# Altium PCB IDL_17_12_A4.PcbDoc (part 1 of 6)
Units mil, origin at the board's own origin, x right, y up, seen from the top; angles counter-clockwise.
Board outline 3172.06 x 10350 mil, 6 copper layers (Top Signal, Mid Signal, 3.3 Volt, GND, 5 Volt, Bot Signal), stack 122.8 mil thick; 332 components, 120 nets, 1937 pads, 197 vias.
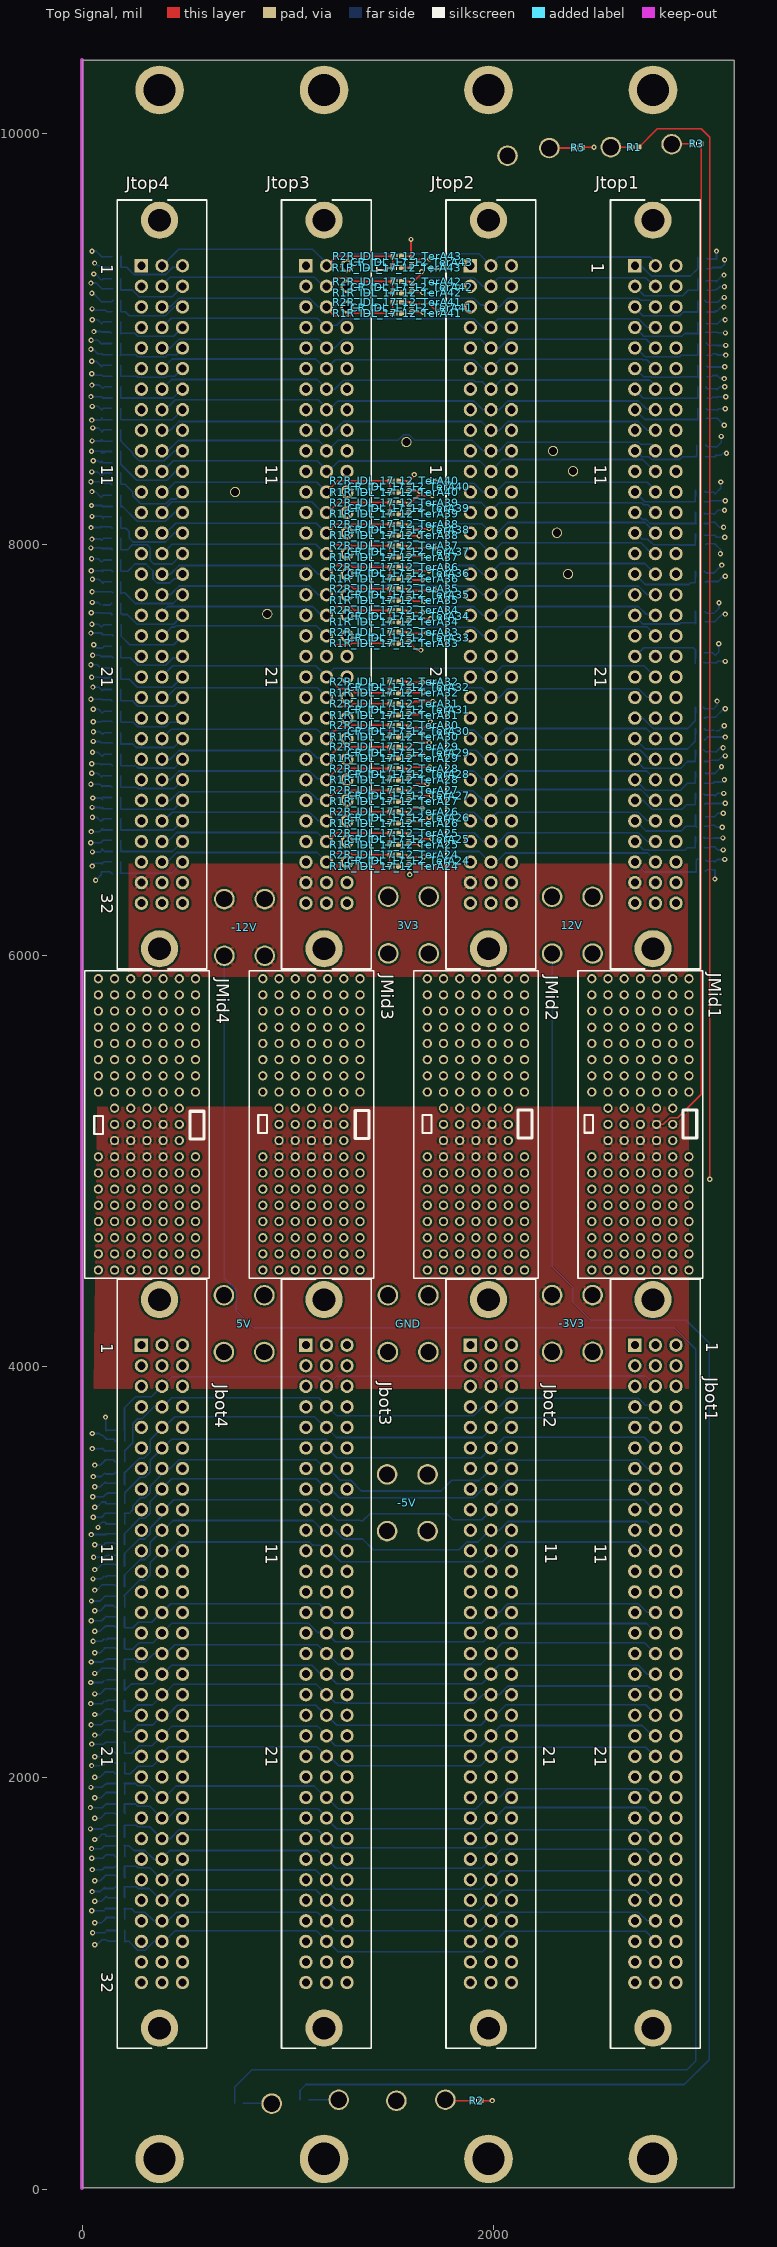
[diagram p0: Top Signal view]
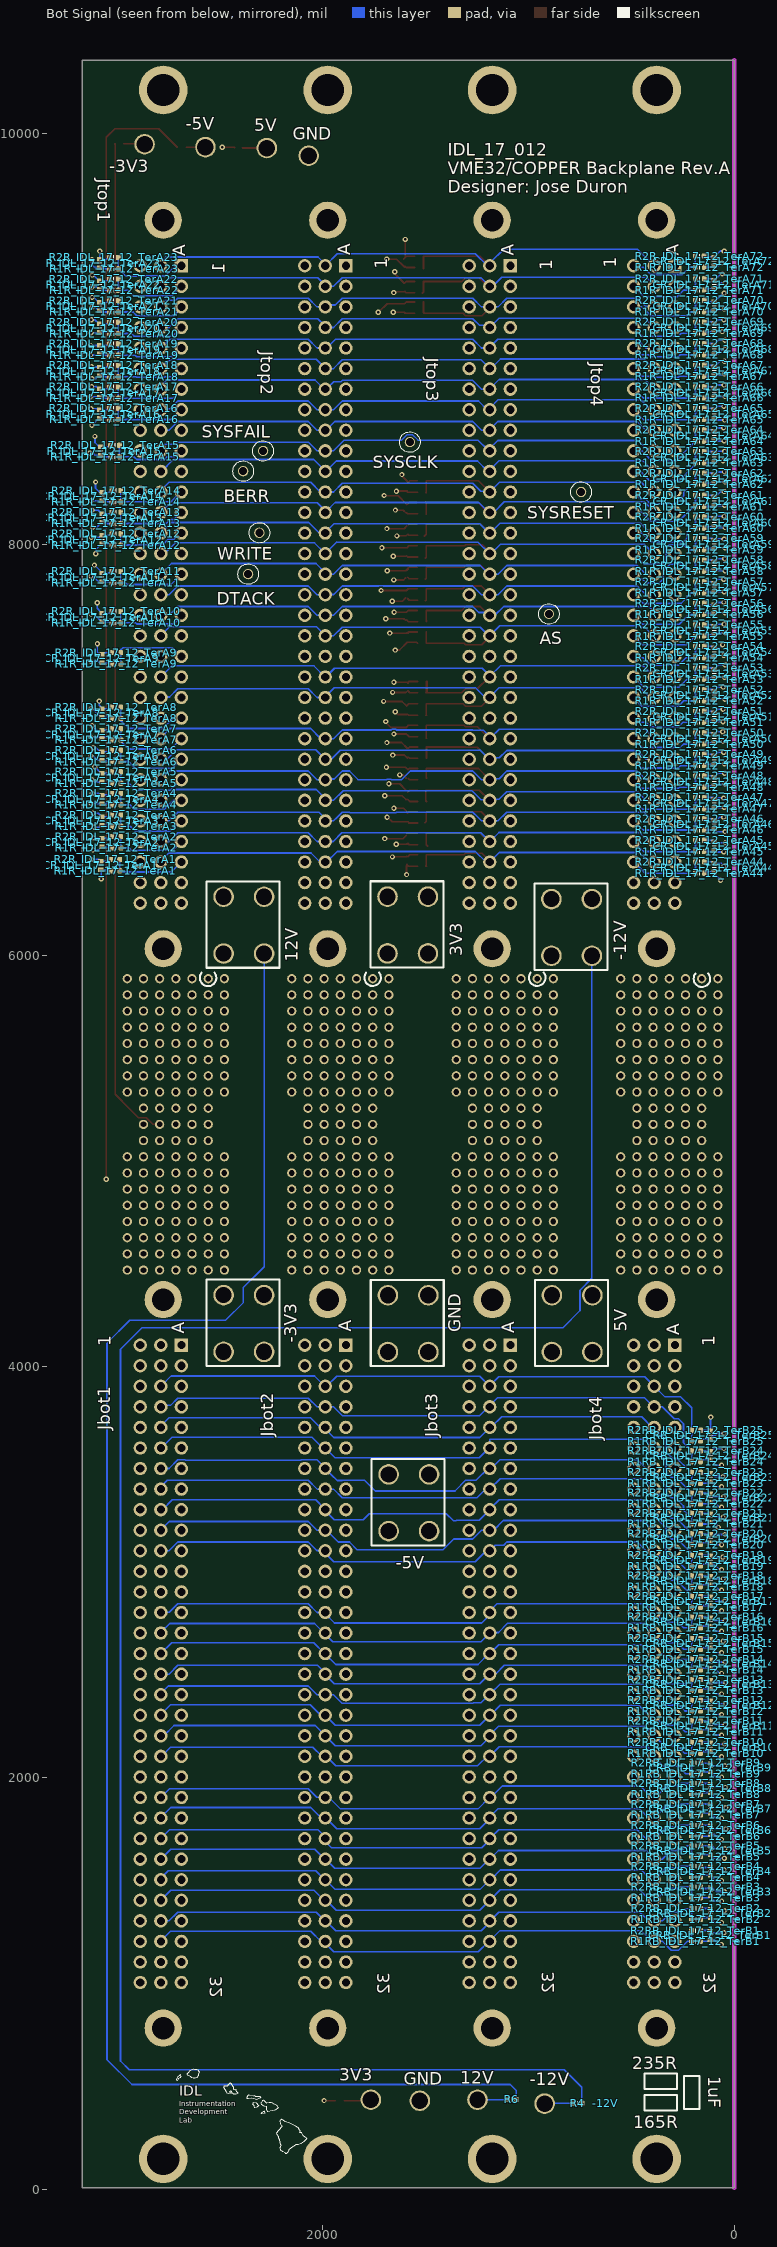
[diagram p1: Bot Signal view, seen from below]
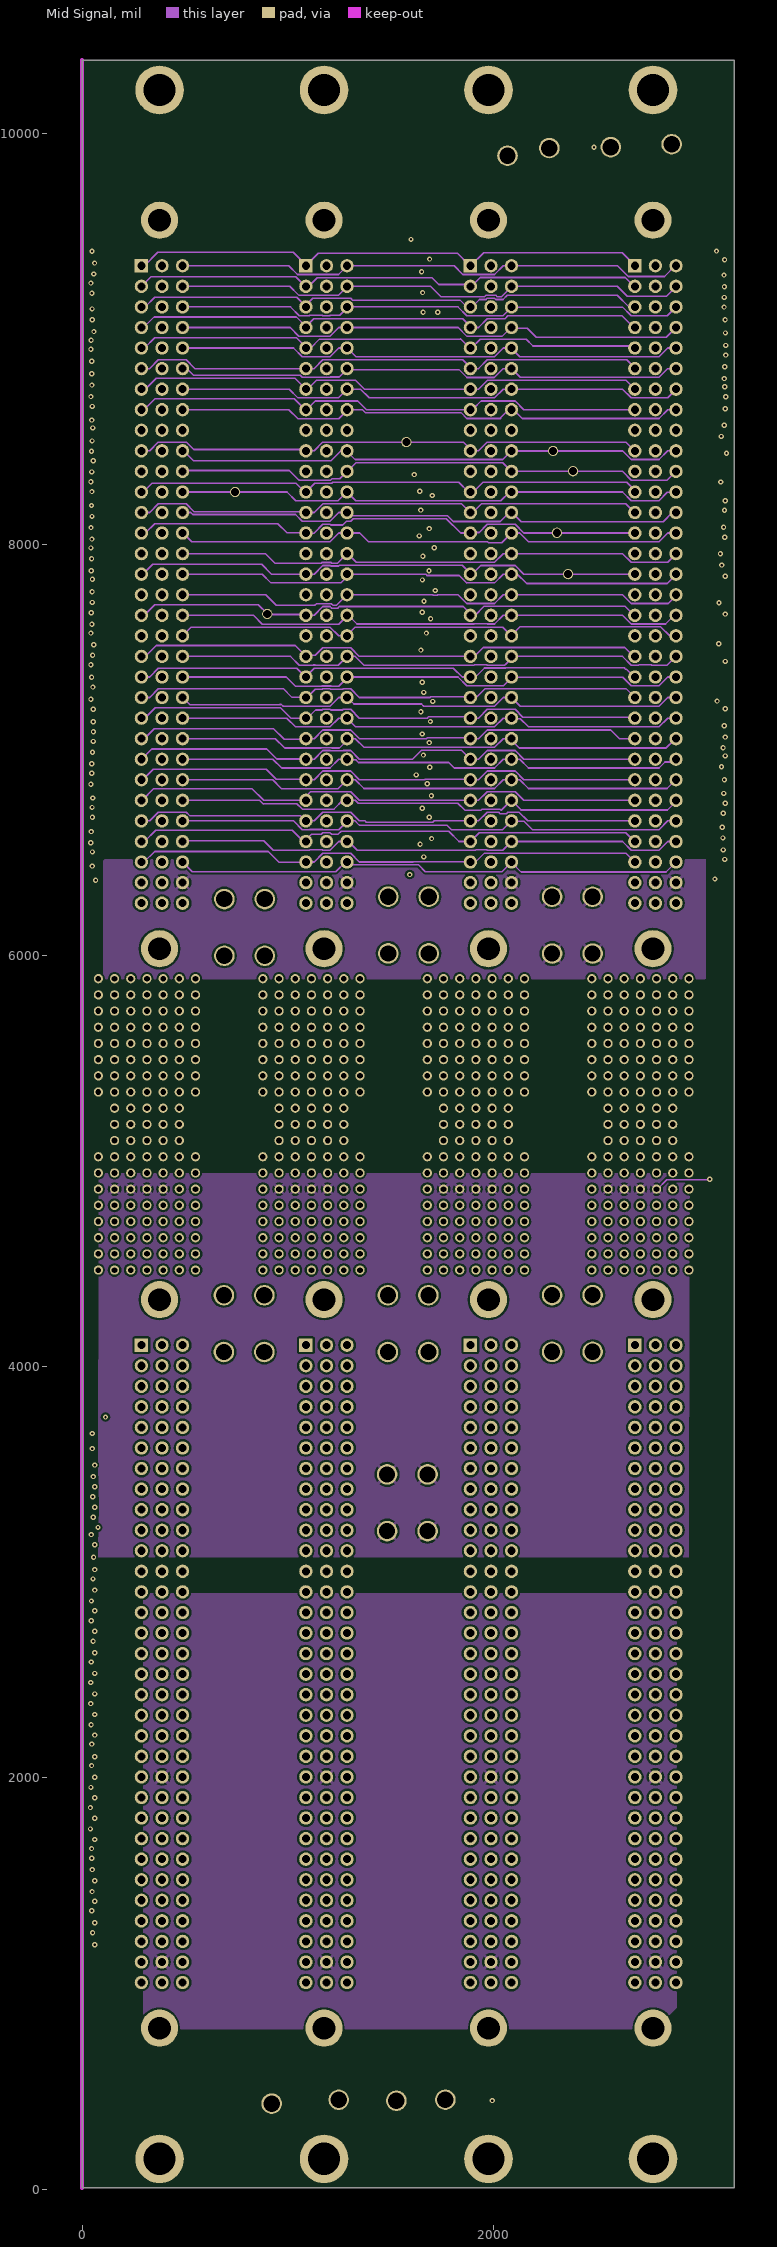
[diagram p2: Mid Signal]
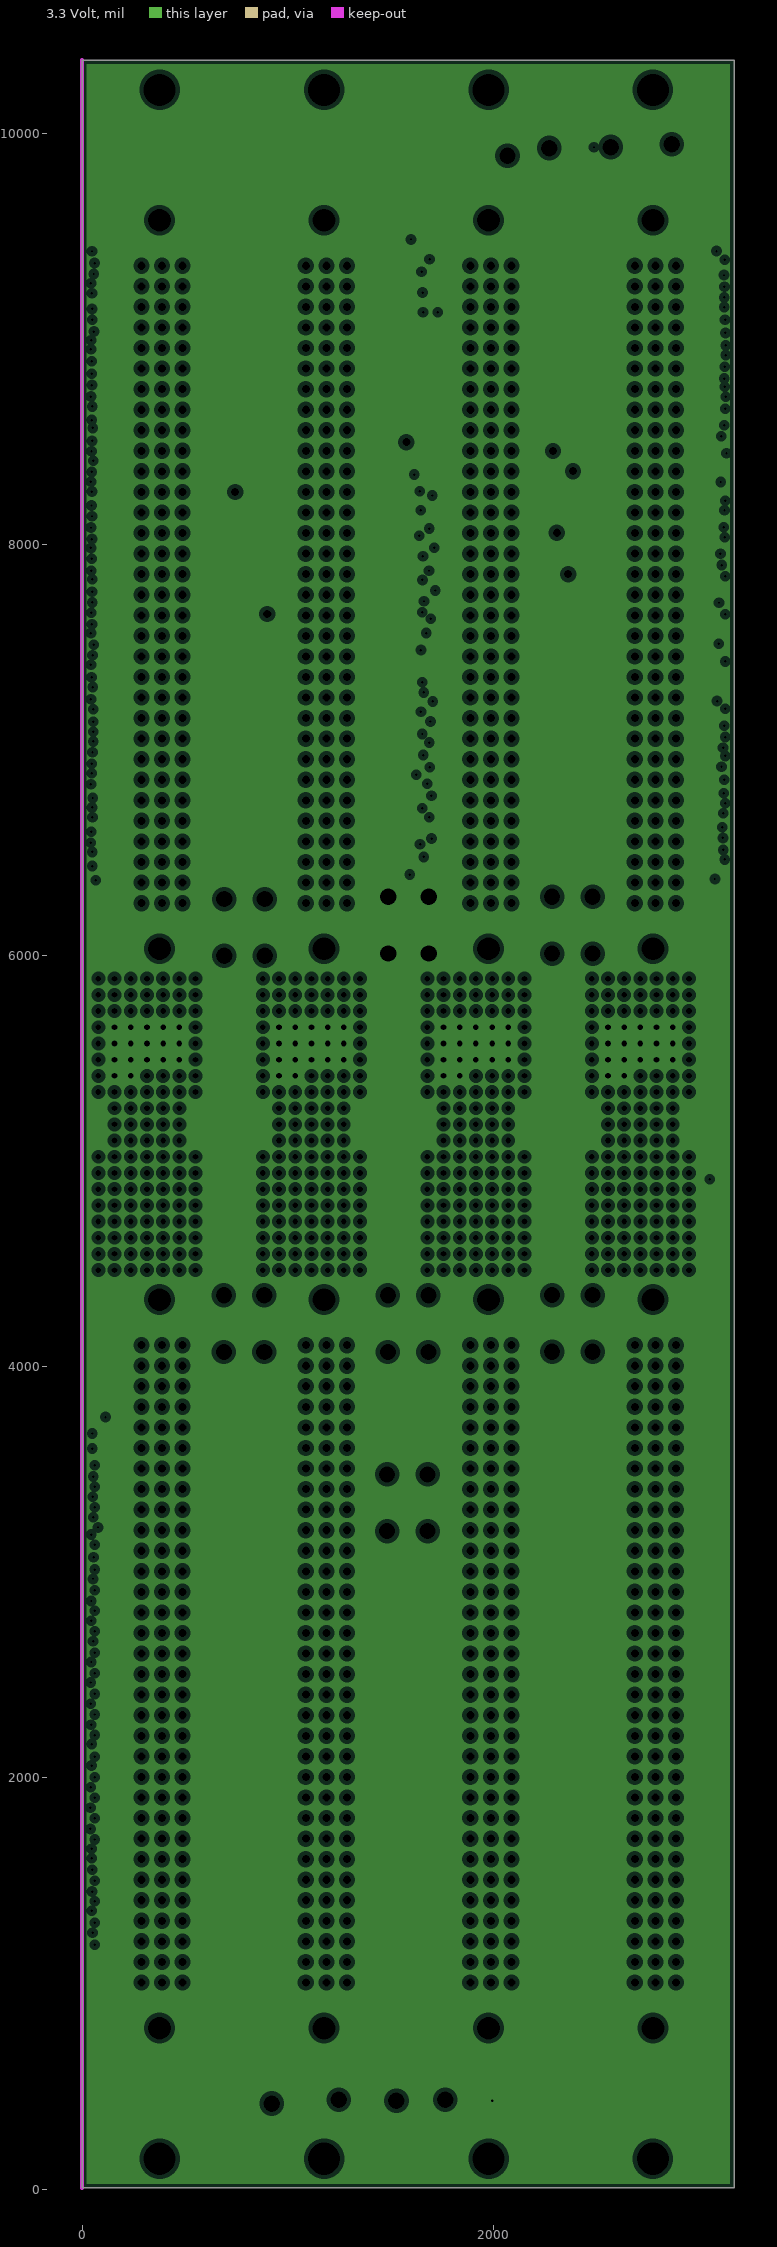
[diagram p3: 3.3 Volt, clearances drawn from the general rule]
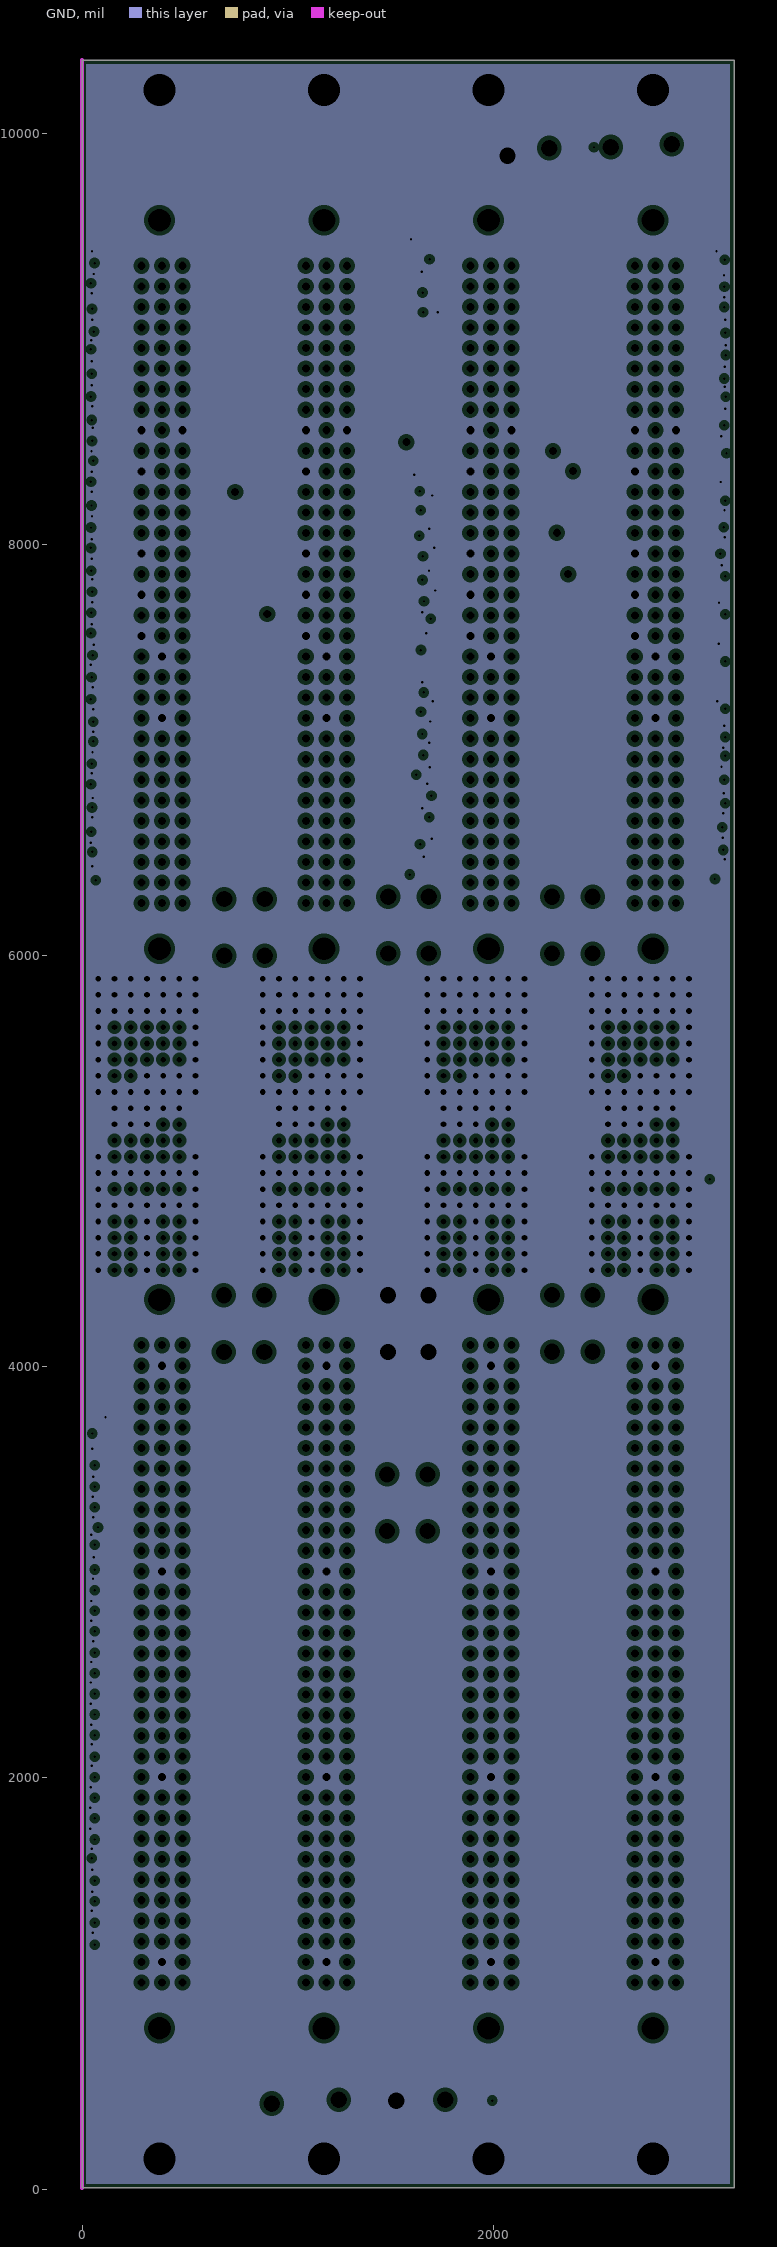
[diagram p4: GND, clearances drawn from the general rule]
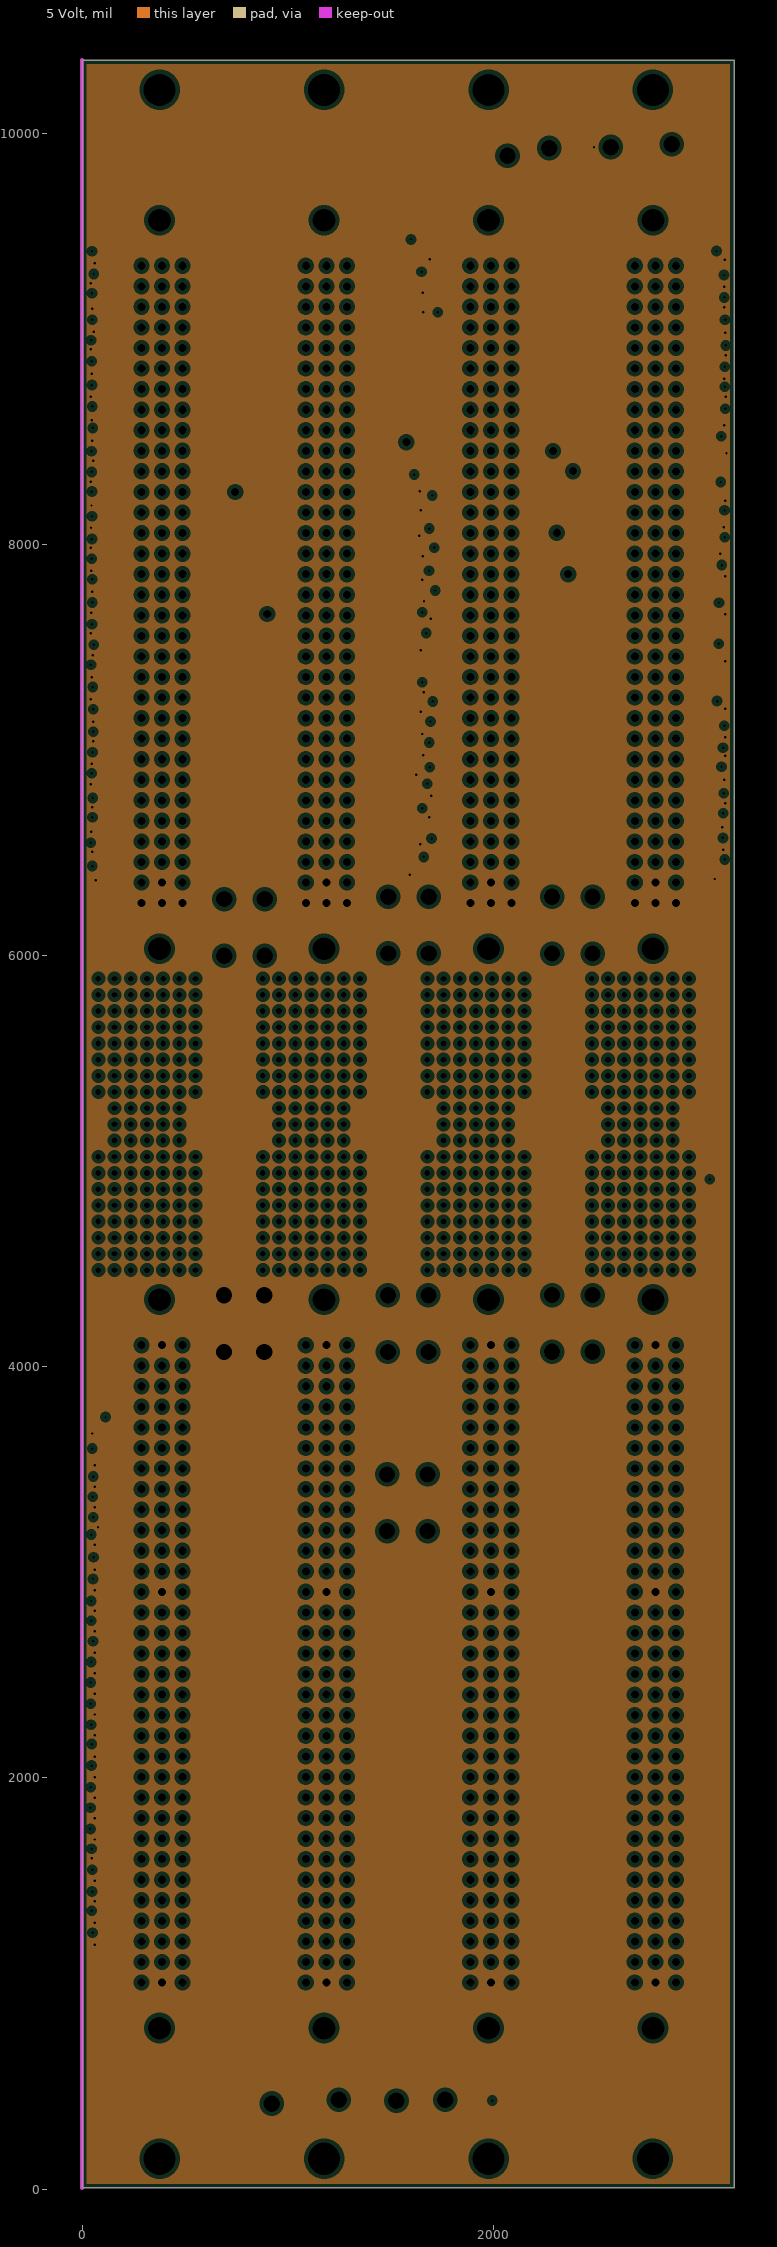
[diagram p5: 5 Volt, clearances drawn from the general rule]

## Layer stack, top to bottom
Top Solder: solder mask 0.4, Solder Resist, Dk 3.5
Top Signal: signal copper 1.35
Dielectric 1: prepreg 10, FR-4, Dk 4.2
Mid Signal: signal copper 1.35
Dielectric 6: core 40, FR-4, Dk 4.2
3.3 Volt: plane copper 2.7, net 3V3
Dielectric 5: prepreg 12, FR-4, Dk 4.2
GND: plane copper 2.7, net GND
Dielectric2: core 40, FR-4, Dk 4.2
5 Volt: plane copper 1.35, net 5V
Dielectric 7: prepreg 10, Dk 4.2
Bot Signal: signal copper 1.35
Bottom Solder: solder mask 0.4, Solder Resist, Dk 3.5

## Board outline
-0.72,10355.73 3171.34,10355.73 3171.34,5.73 -0.72,5.73

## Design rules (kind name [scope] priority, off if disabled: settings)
Clearance "Clearance Polygon" [InNamedPolygon('-12V') or InNamedPolygon('12V')or InNamedPolygon('-3V3')or InNamedPolygon('-5V')or InNamedPolygon('Mid Signal-No Net')] p1: gap=10 ignorepadtopadclearanceinfootprint=FALSE
Clearance "Clearance - Default - DEFAULT- SMD" [IsVia vs IsSMTPin] p2: gap=6 ignorepadtopadclearanceinfootprint=FALSE
Clearance "Clearance - Default - DEFAULT - Via" [IsVia vs IsVia] p3: gap=6 ignorepadtopadclearanceinfootprint=FALSE
Clearance "Clearance - Default - DEFAULT - Net" [All] p4: gap=6 ignorepadtopadclearanceinfootprint=FALSE except(0: Arc-Hole Track-Hole SMDPad-Hole THPad-Hole Via-Hole Fill-Hole Poly-Hole Region-Hole Text-Hole; 10: Text-Text)
ComponentClearance "ComponentClearance - Default - DEFAULT" [All] p1: gap=6 collisioncheckmode=3 verticalgap=10 showdistances=FALSE
DiffPairsRouting [All] p1: maxlimit=10 minlimit=4.02 mostfreqgap=6 toplayer_minwidth=4.02 toplayer_maxwidth=10 toplayer_prefwidth=8 midlayer1_minwidth=4.02 midlayer1_maxwidth=10 midlayer1_prefwidth=8 bottomlayer_minwidth=4.02 bottomlayer_maxwidth=10 bottomlayer_prefwidth=8 maxuncoupledlength=500
FanoutControl Fanout_Small [(CompPinCount < 5)] p3: bgadir=Out bgaviamode=Centered fanoutstyle=Auto fanoutdirection=OutThenIn viagrid=1 // Fanout_Small (Default Rule)
FanoutControl Fanout_SOIC [IsSOIC] p4: bgadir=Out bgaviamode=Centered fanoutstyle=Auto fanoutdirection=Alternating viagrid=1 // Fanout_SOIC (Default Rule)
HoleSize [All] p1: absolutevalues=TRUE maxlimit=200 minlimit=1 maxpercent=80.000 minpercent=20.000
HoleToHoleClearance "HoleToHoleClearance - Default - DEFAULT" [All] p1: gap=6 allowstackedmicrovias=TRUE
Length "Default Length" [All] p1: maxlimit=50000 minlimit=0
MaxMinImpedance "Default Impedance" [All] p1: minimum=50.00 maximum=150.0
MinimumSolderMaskSliver [All] p1: minsoldermaskwidth=5
ParallelSegment "Default Parallel Segment Adjasent" [All] p1: limit=1000 gap=200
ParallelSegment "Default Parallel Segment Same Layer" [All] p2: limit=1000 gap=200
PlaneClearance [All] p1: clearance=20
PlaneConnect "Default PlaneConnect" [All] p1: planeconnectstyle=Relief reliefexpansion=20 reliefentries=4 reliefconductorwidth=15 reliefairgap=10
PolygonConnect "PolygonConnect - Default SMT" [IsSMTPin] p1: connectstyle=Relief reliefconductorwidth=10 reliefentries=4 polygonreliefangle="45 Angle" airgapwidth=10
PolygonConnect "PolygonConnect - Default Pad" [All] p2: connectstyle=Relief reliefconductorwidth=15 reliefentries=4 polygonreliefangle="45 Angle" airgapwidth=10
RoomDefinition IDL_17_12_TerA72 [InComponentClass('IDL_17_12_TerA72')] p1 off: confinementstyle=ConfineIn formatcopy=TRUE lockcomponents=FALSE outline 5386.99,6056.96 5550.78,6056.96 5550.78,6176.38 5386.99,6176.38
RoomDefinition IDL_17_12_TerB25 [InComponentClass('IDL_17_12_TerB25')] p2 off: confinementstyle=ConfineIn formatcopy=TRUE lockcomponents=FALSE outline 3621.28,1764.19 3769.76,1764.19 3769.76,1655.73 3621.28,1655.73
RoomDefinition IDL_17_12_TerB24 [InComponentClass('IDL_17_12_TerB24')] p3 off: confinementstyle=ConfineIn formatcopy=TRUE lockcomponents=FALSE outline 3621.28,1864.19 3769.76,1864.19 3769.76,1755.73 3621.28,1755.73
RoomDefinition IDL_17_12_TerB23 [InComponentClass('IDL_17_12_TerB23')] p4 off: confinementstyle=ConfineIn formatcopy=TRUE lockcomponents=FALSE outline 3621.28,1969.19 3769.76,1969.19 3769.76,1860.73 3621.28,1860.73
RoomDefinition IDL_17_12_TerB22 [InComponentClass('IDL_17_12_TerB22')] p5 off: confinementstyle=ConfineIn formatcopy=TRUE lockcomponents=FALSE outline 3621.28,2069.19 3769.76,2069.19 3769.76,1960.73 3621.28,1960.73
RoomDefinition IDL_17_12_TerB21 [InComponentClass('IDL_17_12_TerB21')] p6 off: confinementstyle=ConfineIn formatcopy=TRUE lockcomponents=FALSE outline 3621.28,2167.19 3769.76,2167.19 3769.76,2058.73 3621.28,2058.73
RoomDefinition IDL_17_12_TerB20 [InComponentClass('IDL_17_12_TerB20')] p7 off: confinementstyle=ConfineIn formatcopy=TRUE lockcomponents=FALSE outline 3621.28,2267.19 3769.76,2267.19 3769.76,2158.73 3621.28,2158.73
RoomDefinition IDL_17_12_TerB19 [InComponentClass('IDL_17_12_TerB19')] p8 off: confinementstyle=ConfineIn formatcopy=TRUE lockcomponents=FALSE outline 3621.28,2372.19 3769.76,2372.19 3769.76,2263.73 3621.28,2263.73
RoomDefinition IDL_17_12_TerB18 [InComponentClass('IDL_17_12_TerB18')] p9 off: confinementstyle=ConfineIn formatcopy=TRUE lockcomponents=FALSE outline 3621.28,2472.19 3769.76,2472.19 3769.76,2363.73 3621.28,2363.73
RoomDefinition IDL_17_12_TerB17 [InComponentClass('IDL_17_12_TerB17')] p10 off: confinementstyle=ConfineIn formatcopy=TRUE lockcomponents=FALSE outline 3621.28,2572.19 3769.76,2572.19 3769.76,2463.73 3621.28,2463.73
RoomDefinition IDL_17_12_TerB16 [InComponentClass('IDL_17_12_TerB16')] p11 off: confinementstyle=ConfineIn formatcopy=TRUE lockcomponents=FALSE outline 3621.28,2672.19 3769.76,2672.19 3769.76,2563.73 3621.28,2563.73
RoomDefinition IDL_17_12_TerB15 [InComponentClass('IDL_17_12_TerB15')] p12 off: confinementstyle=ConfineIn formatcopy=TRUE lockcomponents=FALSE outline 3621.28,2777.19 3769.76,2777.19 3769.76,2668.73 3621.28,2668.73
RoomDefinition IDL_17_12_TerB14 [InComponentClass('IDL_17_12_TerB14')] p13 off: confinementstyle=ConfineIn formatcopy=TRUE lockcomponents=FALSE outline 3621.28,2877.19 3769.76,2877.19 3769.76,2768.73 3621.28,2768.73
RoomDefinition IDL_17_12_TerB13 [InComponentClass('IDL_17_12_TerB13')] p14 off: confinementstyle=ConfineIn formatcopy=TRUE lockcomponents=FALSE outline 3621.28,2977.19 3769.76,2977.19 3769.76,2868.73 3621.28,2868.73
RoomDefinition IDL_17_12_TerB12 [InComponentClass('IDL_17_12_TerB12')] p15 off: confinementstyle=ConfineIn formatcopy=TRUE lockcomponents=FALSE outline 3621.28,3077.19 3769.76,3077.19 3769.76,2968.73 3621.28,2968.73
RoomDefinition IDL_17_12_TerB11 [InComponentClass('IDL_17_12_TerB11')] p16 off: confinementstyle=ConfineIn formatcopy=TRUE lockcomponents=FALSE outline 3621.28,3177.19 3769.76,3177.19 3769.76,3068.73 3621.28,3068.73
RoomDefinition IDL_17_12_TerB10 [InComponentClass('IDL_17_12_TerB10')] p17 off: confinementstyle=ConfineIn formatcopy=TRUE lockcomponents=FALSE outline 3621.28,3282.19 3769.76,3282.19 3769.76,3173.73 3621.28,3173.73
RoomDefinition IDL_17_12_TerB9 [InComponentClass('IDL_17_12_TerB9')] p18 off: confinementstyle=ConfineIn formatcopy=TRUE lockcomponents=FALSE outline 3621.28,3382.19 3769.76,3382.19 3769.76,3273.73 3621.28,3273.73
RoomDefinition IDL_17_12_TerB8 [InComponentClass('IDL_17_12_TerB8')] p19 off: confinementstyle=ConfineIn formatcopy=TRUE lockcomponents=FALSE outline 3621.28,3482.19 3769.76,3482.19 3769.76,3373.73 3621.28,3373.73
RoomDefinition IDL_17_12_TerB7 [InComponentClass('IDL_17_12_TerB7')] p20 off: confinementstyle=ConfineIn formatcopy=TRUE lockcomponents=FALSE outline 3621.28,3582.19 3769.76,3582.19 3769.76,3473.73 3621.28,3473.73
RoomDefinition IDL_17_12_TerB6 [InComponentClass('IDL_17_12_TerB6')] p21 off: confinementstyle=ConfineIn formatcopy=TRUE lockcomponents=FALSE outline 3621.28,3685.19 3769.76,3685.19 3769.76,3576.73 3621.28,3576.73
RoomDefinition IDL_17_12_TerB5 [InComponentClass('IDL_17_12_TerB5')] p22 off: confinementstyle=ConfineIn formatcopy=TRUE lockcomponents=FALSE outline 3621.28,3785.19 3769.76,3785.19 3769.76,3676.73 3621.28,3676.73
RoomDefinition IDL_17_12_TerB4 [InComponentClass('IDL_17_12_TerB4')] p23 off: confinementstyle=ConfineIn formatcopy=TRUE lockcomponents=FALSE outline 3621.28,3885.19 3769.76,3885.19 3769.76,3776.73 3621.28,3776.73
RoomDefinition IDL_17_12_TerB3 [InComponentClass('IDL_17_12_TerB3')] p24 off: confinementstyle=ConfineIn formatcopy=TRUE lockcomponents=FALSE outline 3621.28,3985.19 3769.76,3985.19 3769.76,3876.73 3621.28,3876.73
RoomDefinition IDL_17_12_TerB2 [InComponentClass('IDL_17_12_TerB2')] p25 off: confinementstyle=ConfineIn formatcopy=TRUE lockcomponents=FALSE outline 3621.28,4090.19 3769.76,4090.19 3769.76,3981.73 3621.28,3981.73
RoomDefinition IDL_17_12_TerB1 [InComponentClass('IDL_17_12_TerB1')] p26 off: confinementstyle=ConfineIn formatcopy=TRUE lockcomponents=FALSE outline 3620.59,4197.67 3769.06,4197.67 3769.06,4089.21 3620.59,4089.21
RoomDefinition IDL_17_12_TerA71 [InComponentClass('IDL_17_12_TerA71')] p27 off: confinementstyle=ConfineIn formatcopy=TRUE lockcomponents=FALSE outline 5386.28,6283.44 5535.39,6283.44 5535.39,6176.73 5386.28,6176.73
RoomDefinition IDL_17_12_TerA70 [InComponentClass('IDL_17_12_TerA70')] p28 off: confinementstyle=ConfineIn formatcopy=TRUE lockcomponents=FALSE outline 5386.28,6388.44 5535.39,6388.44 5535.39,6281.73 5386.28,6281.73
RoomDefinition IDL_17_12_TerA69 [InComponentClass('IDL_17_12_TerA69')] p29 off: confinementstyle=ConfineIn formatcopy=TRUE lockcomponents=FALSE outline 5386.28,6493.44 5535.39,6493.44 5535.39,6386.73 5386.28,6386.73
RoomDefinition IDL_17_12_TerA68 [InComponentClass('IDL_17_12_TerA68')] p30 off: confinementstyle=ConfineIn formatcopy=TRUE lockcomponents=FALSE outline 5386.28,6598.44 5535.39,6598.44 5535.39,6491.73 5386.28,6491.73
RoomDefinition IDL_17_12_TerA67 [InComponentClass('IDL_17_12_TerA67')] p31 off: confinementstyle=ConfineIn formatcopy=TRUE lockcomponents=FALSE outline 5386.28,6703.44 5535.39,6703.44 5535.39,6596.73 5386.28,6596.73
RoomDefinition IDL_17_12_TerA66 [InComponentClass('IDL_17_12_TerA66')] p32 off: confinementstyle=ConfineIn formatcopy=TRUE lockcomponents=FALSE outline 5386.28,6808.44 5535.39,6808.44 5535.39,6701.73 5386.28,6701.73
RoomDefinition IDL_17_12_TerA65 [InComponentClass('IDL_17_12_TerA65')] p33 off: confinementstyle=ConfineIn formatcopy=TRUE lockcomponents=FALSE outline 5386.28,6913.44 5535.39,6913.44 5535.39,6806.73 5386.28,6806.73
RoomDefinition IDL_17_12_TerA64 [InComponentClass('IDL_17_12_TerA64')] p34 off: confinementstyle=ConfineIn formatcopy=TRUE lockcomponents=FALSE outline 5386.28,7018.44 5535.39,7018.44 5535.39,6911.73 5386.28,6911.73
RoomDefinition IDL_17_12_TerA63 [InComponentClass('IDL_17_12_TerA63')] p35 off: confinementstyle=ConfineIn formatcopy=TRUE lockcomponents=FALSE outline 5386.28,7123.44 5535.39,7123.44 5535.39,7016.73 5386.28,7016.73
RoomDefinition IDL_17_12_TerA62 [InComponentClass('IDL_17_12_TerA62')] p36 off: confinementstyle=ConfineIn formatcopy=TRUE lockcomponents=FALSE outline 5386.28,7228.44 5535.39,7228.44 5535.39,7121.73 5386.28,7121.73
RoomDefinition IDL_17_12_TerA61 [InComponentClass('IDL_17_12_TerA61')] p37 off: confinementstyle=ConfineIn formatcopy=TRUE lockcomponents=FALSE outline 5386.28,7336.44 5535.39,7336.44 5535.39,7229.73 5386.28,7229.73
RoomDefinition IDL_17_12_TerA60 [InComponentClass('IDL_17_12_TerA60')] p38 off: confinementstyle=ConfineIn formatcopy=TRUE lockcomponents=FALSE outline 5386.28,7441.44 5535.39,7441.44 5535.39,7334.73 5386.28,7334.73
RoomDefinition IDL_17_12_TerA59 [InComponentClass('IDL_17_12_TerA59')] p39 off: confinementstyle=ConfineIn formatcopy=TRUE lockcomponents=FALSE outline 5386.28,7546.44 5535.39,7546.44 5535.39,7439.73 5386.28,7439.73
RoomDefinition IDL_17_12_TerA58 [InComponentClass('IDL_17_12_TerA58')] p40 off: confinementstyle=ConfineIn formatcopy=TRUE lockcomponents=FALSE outline 5386.28,7651.44 5535.39,7651.44 5535.39,7544.73 5386.28,7544.73
RoomDefinition IDL_17_12_TerA57 [InComponentClass('IDL_17_12_TerA57')] p41 off: confinementstyle=ConfineIn formatcopy=TRUE lockcomponents=FALSE outline 5386.28,7756.44 5535.39,7756.44 5535.39,7649.73 5386.28,7649.73
RoomDefinition IDL_17_12_TerA56 [InComponentClass('IDL_17_12_TerA56')] p42 off: confinementstyle=ConfineIn formatcopy=TRUE lockcomponents=FALSE outline 5386.28,7861.44 5535.39,7861.44 5535.39,7754.73 5386.28,7754.73
RoomDefinition IDL_17_12_TerA55 [InComponentClass('IDL_17_12_TerA55')] p43 off: confinementstyle=ConfineIn formatcopy=TRUE lockcomponents=FALSE outline 5386.28,7966.44 5535.39,7966.44 5535.39,7859.73 5386.28,7859.73
RoomDefinition IDL_17_12_TerA54 [InComponentClass('IDL_17_12_TerA54')] p44 off: confinementstyle=ConfineIn formatcopy=TRUE lockcomponents=FALSE outline 5386.28,8071.44 5535.39,8071.44 5535.39,7964.73 5386.28,7964.73
RoomDefinition IDL_17_12_TerA53 [InComponentClass('IDL_17_12_TerA53')] p45 off: confinementstyle=ConfineIn formatcopy=TRUE lockcomponents=FALSE outline 5386.28,8176.44 5535.39,8176.44 5535.39,8069.73 5386.28,8069.73
RoomDefinition IDL_17_12_TerA52 [InComponentClass('IDL_17_12_TerA52')] p46 off: confinementstyle=ConfineIn formatcopy=TRUE lockcomponents=FALSE outline 5386.28,8281.44 5535.39,8281.44 5535.39,8174.73 5386.28,8174.73
RoomDefinition IDL_17_12_TerA51 [InComponentClass('IDL_17_12_TerA51')] p47 off: confinementstyle=ConfineIn formatcopy=TRUE lockcomponents=FALSE outline 5386.28,8386.44 5535.39,8386.44 5535.39,8279.73 5386.28,8279.73
RoomDefinition IDL_17_12_TerA50 [InComponentClass('IDL_17_12_TerA50')] p48 off: confinementstyle=ConfineIn formatcopy=TRUE lockcomponents=FALSE outline 5386.28,8491.44 5535.39,8491.44 5535.39,8384.73 5386.28,8384.73
RoomDefinition IDL_17_12_TerA49 [InComponentClass('IDL_17_12_TerA49')] p49 off: confinementstyle=ConfineIn formatcopy=TRUE lockcomponents=FALSE outline 5386.28,8596.44 5535.39,8596.44 5535.39,8489.73 5386.28,8489.73
RoomDefinition IDL_17_12_TerA48 [InComponentClass('IDL_17_12_TerA48')] p50 off: confinementstyle=ConfineIn formatcopy=TRUE lockcomponents=FALSE outline 5386.28,8701.44 5535.39,8701.44 5535.39,8594.73 5386.28,8594.73
RoomDefinition IDL_17_12_TerA47 [InComponentClass('IDL_17_12_TerA47')] p51 off: confinementstyle=ConfineIn formatcopy=TRUE lockcomponents=FALSE outline 5386.28,8806.44 5535.39,8806.44 5535.39,8699.73 5386.28,8699.73
RoomDefinition IDL_17_12_TerA46 [InComponentClass('IDL_17_12_TerA46')] p52 off: confinementstyle=ConfineIn formatcopy=TRUE lockcomponents=FALSE outline 5386.28,8909.44 5535.39,8909.44 5535.39,8802.73 5386.28,8802.73
RoomDefinition IDL_17_12_TerA45 [InComponentClass('IDL_17_12_TerA45')] p53 off: confinementstyle=ConfineIn formatcopy=TRUE lockcomponents=FALSE outline 5386.28,9014.44 5535.39,9014.44 5535.39,8907.73 5386.28,8907.73
RoomDefinition IDL_17_12_TerA44 [InComponentClass('IDL_17_12_TerA44')] p54 off: confinementstyle=ConfineIn formatcopy=TRUE lockcomponents=FALSE outline 5386.28,9119.44 5535.39,9119.44 5535.39,9012.73 5386.28,9012.73
RoomDefinition IDL_17_12_TerA43 [InComponentClass('IDL_17_12_TerA43')] p55 off: confinementstyle=ConfineIn formatcopy=TRUE lockcomponents=FALSE outline 4514.09,6301.47 4663.2,6301.47 4663.2,6194.76 4514.09,6194.76
RoomDefinition IDL_17_12_TerA42 [InComponentClass('IDL_17_12_TerA42')] p56 off: confinementstyle=ConfineIn formatcopy=TRUE lockcomponents=FALSE outline 4514.16,6424.44 4663.27,6424.44 4663.27,6317.73 4514.16,6317.73
RoomDefinition IDL_17_12_TerA41 [InComponentClass('IDL_17_12_TerA41')] p57 off: confinementstyle=ConfineIn formatcopy=TRUE lockcomponents=FALSE outline 4514.16,6524.44 4663.27,6524.44 4663.27,6417.73 4514.16,6417.73
RoomDefinition IDL_17_12_TerA40 [InComponentClass('IDL_17_12_TerA40')] p58 off: confinementstyle=ConfineIn formatcopy=TRUE lockcomponents=FALSE outline 4521.28,7414.44 4670.39,7414.44 4670.39,7307.73 4521.28,7307.73
RoomDefinition IDL_17_12_TerA39 [InComponentClass('IDL_17_12_TerA39')] p59 off: confinementstyle=ConfineIn formatcopy=TRUE lockcomponents=FALSE outline 4521.28,7519.44 4670.39,7519.44 4670.39,7412.73 4521.28,7412.73
RoomDefinition IDL_17_12_TerA38 [InComponentClass('IDL_17_12_TerA38')] p60 off: confinementstyle=ConfineIn formatcopy=TRUE lockcomponents=FALSE outline 4521.28,7624.44 4670.39,7624.44 4670.39,7517.73 4521.28,7517.73
RoomDefinition IDL_17_12_TerA37 [InComponentClass('IDL_17_12_TerA37')] p61 off: confinementstyle=ConfineIn formatcopy=TRUE lockcomponents=FALSE outline 4521.28,7729.44 4670.39,7729.44 4670.39,7622.73 4521.28,7622.73
RoomDefinition IDL_17_12_TerA36 [InComponentClass('IDL_17_12_TerA36')] p62 off: confinementstyle=ConfineIn formatcopy=TRUE lockcomponents=FALSE outline 4521.28,7834.44 4670.39,7834.44 4670.39,7727.73 4521.28,7727.73
RoomDefinition IDL_17_12_TerA35 [InComponentClass('IDL_17_12_TerA35')] p63 off: confinementstyle=ConfineIn formatcopy=TRUE lockcomponents=FALSE outline 4521.28,7939.44 4670.39,7939.44 4670.39,7832.73 4521.28,7832.73
RoomDefinition IDL_17_12_TerA34 [InComponentClass('IDL_17_12_TerA34')] p64 off: confinementstyle=ConfineIn formatcopy=TRUE lockcomponents=FALSE outline 4521.28,8044.44 4670.39,8044.44 4670.39,7937.73 4521.28,7937.73
RoomDefinition IDL_17_12_TerA33 [InComponentClass('IDL_17_12_TerA33')] p65 off: confinementstyle=ConfineIn formatcopy=TRUE lockcomponents=FALSE outline 4521.28,8149.44 4670.39,8149.44 4670.39,8042.73 4521.28,8042.73
RoomDefinition IDL_17_12_TerA32 [InComponentClass('IDL_17_12_TerA32')] p66 off: confinementstyle=ConfineIn formatcopy=TRUE lockcomponents=FALSE outline 4521.28,8424.44 4670.39,8424.44 4670.39,8317.73 4521.28,8317.73
RoomDefinition IDL_17_12_TerA31 [InComponentClass('IDL_17_12_TerA31')] p67 off: confinementstyle=ConfineIn formatcopy=TRUE lockcomponents=FALSE outline 4521.28,8532.44 4670.39,8532.44 4670.39,8425.73 4521.28,8425.73
RoomDefinition IDL_17_12_TerA30 [InComponentClass('IDL_17_12_TerA30')] p68 off: confinementstyle=ConfineIn formatcopy=TRUE lockcomponents=FALSE outline 4521.28,8637.44 4670.39,8637.44 4670.39,8530.73 4521.28,8530.73
RoomDefinition IDL_17_12_TerA29 [InComponentClass('IDL_17_12_TerA29')] p69 off: confinementstyle=ConfineIn formatcopy=TRUE lockcomponents=FALSE outline 4521.28,8742.44 4670.39,8742.44 4670.39,8635.73 4521.28,8635.73
RoomDefinition IDL_17_12_TerA28 [InComponentClass('IDL_17_12_TerA28')] p70 off: confinementstyle=ConfineIn formatcopy=TRUE lockcomponents=FALSE outline 4521.28,8847.44 4670.39,8847.44 4670.39,8740.73 4521.28,8740.73
RoomDefinition IDL_17_12_TerA27 [InComponentClass('IDL_17_12_TerA27')] p71 off: confinementstyle=ConfineIn formatcopy=TRUE lockcomponents=FALSE outline 4521.28,8952.44 4670.39,8952.44 4670.39,8845.73 4521.28,8845.73
RoomDefinition IDL_17_12_TerA26 [InComponentClass('IDL_17_12_TerA26')] p72 off: confinementstyle=ConfineIn formatcopy=TRUE lockcomponents=FALSE outline 4521.28,9057.44 4670.39,9057.44 4670.39,8950.73 4521.28,8950.73
RoomDefinition IDL_17_12_TerA25 [InComponentClass('IDL_17_12_TerA25')] p73 off: confinementstyle=ConfineIn formatcopy=TRUE lockcomponents=FALSE outline 4521.28,9162.44 4670.39,9162.44 4670.39,9055.73 4521.28,9055.73
RoomDefinition IDL_17_12_TerA24 [InComponentClass('IDL_17_12_TerA24')] p74 off: confinementstyle=ConfineIn formatcopy=TRUE lockcomponents=FALSE outline 4521.28,9267.44 4670.39,9267.44 4670.39,9160.73 4521.28,9160.73
RoomDefinition IDL_17_12_TerA23 [InComponentClass('IDL_17_12_TerA23')] p75 off: confinementstyle=ConfineIn formatcopy=TRUE lockcomponents=FALSE outline 3659.19,6324.92 3808.3,6324.92 3808.3,6218.21 3659.19,6218.21
RoomDefinition IDL_17_12_TerA22 [InComponentClass('IDL_17_12_TerA22')] p76 off: confinementstyle=ConfineIn formatcopy=TRUE lockcomponents=FALSE outline 3659.19,6429.92 3808.3,6429.92 3808.3,6323.21 3659.19,6323.21
RoomDefinition IDL_17_12_TerA21 [InComponentClass('IDL_17_12_TerA21')] p77 off: confinementstyle=ConfineIn formatcopy=TRUE lockcomponents=FALSE outline 3659.19,6534.92 3808.3,6534.92 3808.3,6428.21 3659.19,6428.21
RoomDefinition IDL_17_12_TerA20 [InComponentClass('IDL_17_12_TerA20')] p78 off: confinementstyle=ConfineIn formatcopy=TRUE lockcomponents=FALSE outline 3659.19,6639.92 3808.3,6639.92 3808.3,6533.21 3659.19,6533.21
RoomDefinition IDL_17_12_TerA19 [InComponentClass('IDL_17_12_TerA19')] p79 off: confinementstyle=ConfineIn formatcopy=TRUE lockcomponents=FALSE outline 3659.19,6744.92 3808.3,6744.92 3808.3,6638.21 3659.19,6638.21
RoomDefinition IDL_17_12_TerA18 [InComponentClass('IDL_17_12_TerA18')] p80 off: confinementstyle=ConfineIn formatcopy=TRUE lockcomponents=FALSE outline 3659.19,6849.92 3808.3,6849.92 3808.3,6743.21 3659.19,6743.21
RoomDefinition IDL_17_12_TerA17 [InComponentClass('IDL_17_12_TerA17')] p81 off: confinementstyle=ConfineIn formatcopy=TRUE lockcomponents=FALSE outline 3659.19,6954.92 3808.3,6954.92 3808.3,6848.21 3659.19,6848.21
RoomDefinition IDL_17_12_TerA16 [InComponentClass('IDL_17_12_TerA16')] p82 off: confinementstyle=ConfineIn formatcopy=TRUE lockcomponents=FALSE outline 3659.19,7057.92 3808.3,7057.92 3808.3,6951.21 3659.19,6951.21
RoomDefinition IDL_17_12_TerA15 [InComponentClass('IDL_17_12_TerA15')] p83 off: confinementstyle=ConfineIn formatcopy=TRUE lockcomponents=FALSE outline 3506.92,7227.28 3656.03,7227.28 3656.03,7120.58 3506.92,7120.58
RoomDefinition IDL_17_12_TerA14 [InComponentClass('IDL_17_12_TerA14')] p84 off: confinementstyle=ConfineIn formatcopy=TRUE lockcomponents=FALSE outline 3500.91,7447.22 3650.03,7447.22 3650.03,7340.52 3500.91,7340.52
RoomDefinition IDL_17_12_TerA13 [InComponentClass('IDL_17_12_TerA13')] p85 off: confinementstyle=ConfineIn formatcopy=TRUE lockcomponents=FALSE outline 3500.91,7552.22 3650.03,7552.22 3650.03,7445.52 3500.91,7445.52
RoomDefinition IDL_17_12_TerA12 [InComponentClass('IDL_17_12_TerA12')] p86 off: confinementstyle=ConfineIn formatcopy=TRUE lockcomponents=FALSE outline 3500.91,7657.22 3650.03,7657.22 3650.03,7550.52 3500.91,7550.52
RoomDefinition IDL_17_12_TerA11 [InComponentClass('IDL_17_12_TerA11')] p87 off: confinementstyle=ConfineIn formatcopy=TRUE lockcomponents=FALSE outline 3501.28,7840.44 3650.39,7840.44 3650.39,7733.73 3501.28,7733.73
RoomDefinition IDL_17_12_TerA10 [InComponentClass('IDL_17_12_TerA10')] p88 off: confinementstyle=ConfineIn formatcopy=TRUE lockcomponents=FALSE outline 3501.28,8035.44 3650.39,8035.44 3650.39,7928.73 3501.28,7928.73
RoomDefinition IDL_17_12_TerA9 [InComponentClass('IDL_17_12_TerA9')] p89 off: confinementstyle=ConfineIn formatcopy=TRUE lockcomponents=FALSE outline 3501.28,8235.44 3650.39,8235.44 3650.39,8128.73 3501.28,8128.73
RoomDefinition IDL_17_12_TerA8 [InComponentClass('IDL_17_12_TerA8')] p90 off: confinementstyle=ConfineIn formatcopy=TRUE lockcomponents=TRUE outline 3501.28,8500.44 3650.39,8500.44 3650.39,8393.73 3501.28,8393.73
RoomDefinition IDL_17_12_TerA7 [InComponentClass('IDL_17_12_TerA7')] p91 off: confinementstyle=ConfineIn formatcopy=TRUE lockcomponents=FALSE outline 3501.28,8605.44 3650.39,8605.44 3650.39,8498.73 3501.28,8498.73
RoomDefinition IDL_17_12_TerA6 [InComponentClass('IDL_17_12_TerA6')] p92 off: confinementstyle=ConfineIn formatcopy=TRUE lockcomponents=FALSE outline 3501.28,8710.44 3650.39,8710.44 3650.39,8603.73 3501.28,8603.73
RoomDefinition IDL_17_12_TerA5 [InComponentClass('IDL_17_12_TerA5')] p93 off: confinementstyle=ConfineIn formatcopy=TRUE lockcomponents=FALSE outline 3501.28,8815.44 3650.39,8815.44 3650.39,8708.73 3501.28,8708.73
RoomDefinition IDL_17_12_TerA4 [InComponentClass('IDL_17_12_TerA4')] p94 off: confinementstyle=ConfineIn formatcopy=TRUE lockcomponents=FALSE outline 3501.28,8920.44 3650.39,8920.44 3650.39,8813.73 3501.28,8813.73
RoomDefinition IDL_17_12_TerA3 [InComponentClass('IDL_17_12_TerA3')] p95 off: confinementstyle=ConfineIn formatcopy=TRUE lockcomponents=FALSE outline 3501.28,9025.44 3650.39,9025.44 3650.39,8918.73 3501.28,8918.73
RoomDefinition IDL_17_12_TerA2 [InComponentClass('IDL_17_12_TerA2')] p96 off: confinementstyle=ConfineIn formatcopy=TRUE lockcomponents=FALSE outline 3501.28,9130.44 3650.39,9130.44 3650.39,9023.73 3501.28,9023.73
RoomDefinition IDL_17_12_TerA1 [InComponentClass('IDL_17_12_TerA1')] p97 off: confinementstyle=ConfineIn formatcopy=TRUE lockcomponents=TRUE outline 3506.28,9241.67 3655.39,9241.67 3655.39,9134.97 3506.28,9134.97
RoutingLayers "RoutingLayers - Default - DEFAULT" [All] p1: top layer_v5=TRUE mid layer 1_v5=TRUE bottom layer_v5=TRUE
RoutingPriority "RoutingPriority - Default - DEFAULT" [All] p1: routingpriority=3
RoutingTopology "Default Routing Topology" [All] p1: topology=Shortest
RoutingVias "RoutingVias - Default - DEFAULT" [All] p1: holewidth=12 width=25.59 viastyle="Through Hole" minholewidth=12 minwidth=25.59 maxholewidth=12 maxwidth=25.59
SMDToCorner "SMDToCorner - Default - DEFAULT" [All] p1: distance=60000
SilkToSilkClearance [All] p1: silktosilkclearance=5
SilkToSolderMaskClearance [IsPad] p1: minsilkscreentomaskgap=5 clearancetoexposedcopper=TRUE
SolderMaskExpansion [All] p1: expansion=4
Width "Default Width" [All] p1: maxlimit=150 minlimit=8 preferedwidth=8
16 further rules are at their usual default settings.

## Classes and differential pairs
component class IDL_17_12_TerA72: CR_IDL_17_12_TerA72 R1R_IDL_17_12_TerA72 R2R_IDL_17_12_TerA72
component class IDL_17_12_J0: JMid1 JMid2 JMid3 JMid4
component class IDL_17_12_J1: Jtop1 Jtop2 Jtop3 Jtop4
component class IDL_17_12_J2: Jbot1 Jbot2 Jbot3 Jbot4
component class IDL_17_12_TerA1: CR_IDL_17_12_TerA1 R1R_IDL_17_12_TerA1 R2R_IDL_17_12_TerA1
component class IDL_17_12_TerA2: CR_IDL_17_12_TerA2 R1R_IDL_17_12_TerA2 R2R_IDL_17_12_TerA2
component class IDL_17_12_TerA3: CR_IDL_17_12_TerA3 R1R_IDL_17_12_TerA3 R2R_IDL_17_12_TerA3
component class IDL_17_12_TerA4: CR_IDL_17_12_TerA4 R1R_IDL_17_12_TerA4 R2R_IDL_17_12_TerA4
component class IDL_17_12_TerA5: CR_IDL_17_12_TerA5 R1R_IDL_17_12_TerA5 R2R_IDL_17_12_TerA5
component class IDL_17_12_TerA6: CR_IDL_17_12_TerA6 R1R_IDL_17_12_TerA6 R2R_IDL_17_12_TerA6
component class IDL_17_12_TerA7: CR_IDL_17_12_TerA7 R1R_IDL_17_12_TerA7 R2R_IDL_17_12_TerA7
component class IDL_17_12_TerA8: CR_IDL_17_12_TerA8 R1R_IDL_17_12_TerA8 R2R_IDL_17_12_TerA8
component class IDL_17_12_TerA9: CR_IDL_17_12_TerA9 R1R_IDL_17_12_TerA9 R2R_IDL_17_12_TerA9
component class IDL_17_12_TerA10: CR_IDL_17_12_TerA10 R1R_IDL_17_12_TerA10 R2R_IDL_17_12_TerA10
component class IDL_17_12_TerA11: CR_IDL_17_12_TerA11 R1R_IDL_17_12_TerA11 R2R_IDL_17_12_TerA11
component class IDL_17_12_TerA12: CR_IDL_17_12_TerA12 R1R_IDL_17_12_TerA12 R2R_IDL_17_12_TerA12
component class IDL_17_12_TerA13: CR_IDL_17_12_TerA13 R1R_IDL_17_12_TerA13 R2R_IDL_17_12_TerA13
component class IDL_17_12_TerA14: CR_IDL_17_12_TerA14 R1R_IDL_17_12_TerA14 R2R_IDL_17_12_TerA14
component class IDL_17_12_TerA15: CR_IDL_17_12_TerA15 R1R_IDL_17_12_TerA15 R2R_IDL_17_12_TerA15
component class IDL_17_12_TerA16: CR_IDL_17_12_TerA16 R1R_IDL_17_12_TerA16 R2R_IDL_17_12_TerA16
component class IDL_17_12_TerA17: CR_IDL_17_12_TerA17 R1R_IDL_17_12_TerA17 R2R_IDL_17_12_TerA17
component class IDL_17_12_TerA18: CR_IDL_17_12_TerA18 R1R_IDL_17_12_TerA18 R2R_IDL_17_12_TerA18
component class IDL_17_12_TerA19: CR_IDL_17_12_TerA19 R1R_IDL_17_12_TerA19 R2R_IDL_17_12_TerA19
component class IDL_17_12_TerA20: CR_IDL_17_12_TerA20 R1R_IDL_17_12_TerA20 R2R_IDL_17_12_TerA20
component class IDL_17_12_TerA21: CR_IDL_17_12_TerA21 R1R_IDL_17_12_TerA21 R2R_IDL_17_12_TerA21
component class IDL_17_12_TerA22: CR_IDL_17_12_TerA22 R1R_IDL_17_12_TerA22 R2R_IDL_17_12_TerA22
component class IDL_17_12_TerA23: CR_IDL_17_12_TerA23 R1R_IDL_17_12_TerA23 R2R_IDL_17_12_TerA23
component class IDL_17_12_TerA24: CR_IDL_17_12_TerA24 R1R_IDL_17_12_TerA24 R2R_IDL_17_12_TerA24
component class IDL_17_12_TerA25: CR_IDL_17_12_TerA25 R1R_IDL_17_12_TerA25 R2R_IDL_17_12_TerA25
component class IDL_17_12_TerA26: CR_IDL_17_12_TerA26 R1R_IDL_17_12_TerA26 R2R_IDL_17_12_TerA26
component class IDL_17_12_TerA27: CR_IDL_17_12_TerA27 R1R_IDL_17_12_TerA27 R2R_IDL_17_12_TerA27
component class IDL_17_12_TerA28: CR_IDL_17_12_TerA28 R1R_IDL_17_12_TerA28 R2R_IDL_17_12_TerA28
component class IDL_17_12_TerA29: CR_IDL_17_12_TerA29 R1R_IDL_17_12_TerA29 R2R_IDL_17_12_TerA29
component class IDL_17_12_TerA30: CR_IDL_17_12_TerA30 R1R_IDL_17_12_TerA30 R2R_IDL_17_12_TerA30
component class IDL_17_12_TerA31: CR_IDL_17_12_TerA31 R1R_IDL_17_12_TerA31 R2R_IDL_17_12_TerA31
component class IDL_17_12_TerA32: CR_IDL_17_12_TerA32 R1R_IDL_17_12_TerA32 R2R_IDL_17_12_TerA32
component class IDL_17_12_TerA33: CR_IDL_17_12_TerA33 R1R_IDL_17_12_TerA33 R2R_IDL_17_12_TerA33
component class IDL_17_12_TerA34: CR_IDL_17_12_TerA34 R1R_IDL_17_12_TerA34 R2R_IDL_17_12_TerA34
component class IDL_17_12_TerA35: CR_IDL_17_12_TerA35 R1R_IDL_17_12_TerA35 R2R_IDL_17_12_TerA35
component class IDL_17_12_TerA36: CR_IDL_17_12_TerA36 R1R_IDL_17_12_TerA36 R2R_IDL_17_12_TerA36
component class IDL_17_12_TerA37: CR_IDL_17_12_TerA37 R1R_IDL_17_12_TerA37 R2R_IDL_17_12_TerA37
component class IDL_17_12_TerA38: CR_IDL_17_12_TerA38 R1R_IDL_17_12_TerA38 R2R_IDL_17_12_TerA38
component class IDL_17_12_TerA39: CR_IDL_17_12_TerA39 R1R_IDL_17_12_TerA39 R2R_IDL_17_12_TerA39
component class IDL_17_12_TerA40: CR_IDL_17_12_TerA40 R1R_IDL_17_12_TerA40 R2R_IDL_17_12_TerA40
component class IDL_17_12_TerA41: CR_IDL_17_12_TerA41 R1R_IDL_17_12_TerA41 R2R_IDL_17_12_TerA41
component class IDL_17_12_TerA42: CR_IDL_17_12_TerA42 R1R_IDL_17_12_TerA42 R2R_IDL_17_12_TerA42
component class IDL_17_12_TerA43: CR_IDL_17_12_TerA43 R1R_IDL_17_12_TerA43 R2R_IDL_17_12_TerA43
component class IDL_17_12_TerA44: CR_IDL_17_12_TerA44 R1R_IDL_17_12_TerA44 R2R_IDL_17_12_TerA44
component class IDL_17_12_TerA45: CR_IDL_17_12_TerA45 R1R_IDL_17_12_TerA45 R2R_IDL_17_12_TerA45
component class IDL_17_12_TerA46: CR_IDL_17_12_TerA46 R1R_IDL_17_12_TerA46 R2R_IDL_17_12_TerA46
component class IDL_17_12_TerA47: CR_IDL_17_12_TerA47 R1R_IDL_17_12_TerA47 R2R_IDL_17_12_TerA47
component class IDL_17_12_TerA48: CR_IDL_17_12_TerA48 R1R_IDL_17_12_TerA48 R2R_IDL_17_12_TerA48
component class IDL_17_12_TerA49: CR_IDL_17_12_TerA49 R1R_IDL_17_12_TerA49 R2R_IDL_17_12_TerA49
component class IDL_17_12_TerA50: CR_IDL_17_12_TerA50 R1R_IDL_17_12_TerA50 R2R_IDL_17_12_TerA50
component class IDL_17_12_TerA51: CR_IDL_17_12_TerA51 R1R_IDL_17_12_TerA51 R2R_IDL_17_12_TerA51
component class IDL_17_12_TerA52: CR_IDL_17_12_TerA52 R1R_IDL_17_12_TerA52 R2R_IDL_17_12_TerA52
component class IDL_17_12_TerA53: CR_IDL_17_12_TerA53 R1R_IDL_17_12_TerA53 R2R_IDL_17_12_TerA53
component class IDL_17_12_TerA54: CR_IDL_17_12_TerA54 R1R_IDL_17_12_TerA54 R2R_IDL_17_12_TerA54
component class IDL_17_12_TerA55: CR_IDL_17_12_TerA55 R1R_IDL_17_12_TerA55 R2R_IDL_17_12_TerA55
component class IDL_17_12_TerA56: CR_IDL_17_12_TerA56 R1R_IDL_17_12_TerA56 R2R_IDL_17_12_TerA56
component class IDL_17_12_TerA57: CR_IDL_17_12_TerA57 R1R_IDL_17_12_TerA57 R2R_IDL_17_12_TerA57
component class IDL_17_12_TerA58: CR_IDL_17_12_TerA58 R1R_IDL_17_12_TerA58 R2R_IDL_17_12_TerA58
component class IDL_17_12_TerA59: CR_IDL_17_12_TerA59 R1R_IDL_17_12_TerA59 R2R_IDL_17_12_TerA59
component class IDL_17_12_TerA60: CR_IDL_17_12_TerA60 R1R_IDL_17_12_TerA60 R2R_IDL_17_12_TerA60
component class IDL_17_12_TerA61: CR_IDL_17_12_TerA61 R1R_IDL_17_12_TerA61 R2R_IDL_17_12_TerA61
component class IDL_17_12_TerA62: CR_IDL_17_12_TerA62 R1R_IDL_17_12_TerA62 R2R_IDL_17_12_TerA62
component class IDL_17_12_TerA63: CR_IDL_17_12_TerA63 R1R_IDL_17_12_TerA63 R2R_IDL_17_12_TerA63
component class IDL_17_12_TerA64: CR_IDL_17_12_TerA64 R1R_IDL_17_12_TerA64 R2R_IDL_17_12_TerA64
component class IDL_17_12_TerA65: CR_IDL_17_12_TerA65 R1R_IDL_17_12_TerA65 R2R_IDL_17_12_TerA65
component class IDL_17_12_TerA66: CR_IDL_17_12_TerA66 R1R_IDL_17_12_TerA66 R2R_IDL_17_12_TerA66
component class IDL_17_12_TerA67: CR_IDL_17_12_TerA67 R1R_IDL_17_12_TerA67 R2R_IDL_17_12_TerA67
component class IDL_17_12_TerA68: CR_IDL_17_12_TerA68 R1R_IDL_17_12_TerA68 R2R_IDL_17_12_TerA68
component class IDL_17_12_TerA69: CR_IDL_17_12_TerA69 R1R_IDL_17_12_TerA69 R2R_IDL_17_12_TerA69
component class IDL_17_12_TerA70: CR_IDL_17_12_TerA70 R1R_IDL_17_12_TerA70 R2R_IDL_17_12_TerA70
component class IDL_17_12_TerA71: CR_IDL_17_12_TerA71 R1R_IDL_17_12_TerA71 R2R_IDL_17_12_TerA71
component class IDL_17_12_TerB1: CRB_IDL_17_12_TerB1 R1RB_IDL_17_12_TerB1 R2RB_IDL_17_12_TerB1
component class IDL_17_12_TerB2: CRB_IDL_17_12_TerB2 R1RB_IDL_17_12_TerB2 R2RB_IDL_17_12_TerB2
component class IDL_17_12_TerB3: CRB_IDL_17_12_TerB3 R1RB_IDL_17_12_TerB3 R2RB_IDL_17_12_TerB3
component class IDL_17_12_TerB4: CRB_IDL_17_12_TerB4 R1RB_IDL_17_12_TerB4 R2RB_IDL_17_12_TerB4
component class IDL_17_12_TerB5: CRB_IDL_17_12_TerB5 R1RB_IDL_17_12_TerB5 R2RB_IDL_17_12_TerB5
component class IDL_17_12_TerB6: CRB_IDL_17_12_TerB6 R1RB_IDL_17_12_TerB6 R2RB_IDL_17_12_TerB6
component class IDL_17_12_TerB7: CRB_IDL_17_12_TerB7 R1RB_IDL_17_12_TerB7 R2RB_IDL_17_12_TerB7
component class IDL_17_12_TerB8: CRB_IDL_17_12_TerB8 R1RB_IDL_17_12_TerB8 R2RB_IDL_17_12_TerB8
component class IDL_17_12_TerB9: CRB_IDL_17_12_TerB9 R1RB_IDL_17_12_TerB9 R2RB_IDL_17_12_TerB9
component class IDL_17_12_TerB10: CRB_IDL_17_12_TerB10 R1RB_IDL_17_12_TerB10 R2RB_IDL_17_12_TerB10
component class IDL_17_12_TerB11: CRB_IDL_17_12_TerB11 R1RB_IDL_17_12_TerB11 R2RB_IDL_17_12_TerB11
component class IDL_17_12_TerB12: CRB_IDL_17_12_TerB12 R1RB_IDL_17_12_TerB12 R2RB_IDL_17_12_TerB12
component class IDL_17_12_TerB13: CRB_IDL_17_12_TerB13 R1RB_IDL_17_12_TerB13 R2RB_IDL_17_12_TerB13
component class IDL_17_12_TerB14: CRB_IDL_17_12_TerB14 R1RB_IDL_17_12_TerB14 R2RB_IDL_17_12_TerB14
component class IDL_17_12_TerB15: CRB_IDL_17_12_TerB15 R1RB_IDL_17_12_TerB15 R2RB_IDL_17_12_TerB15
component class IDL_17_12_TerB16: CRB_IDL_17_12_TerB16 R1RB_IDL_17_12_TerB16 R2RB_IDL_17_12_TerB16
component class IDL_17_12_TerB17: CRB_IDL_17_12_TerB17 R1RB_IDL_17_12_TerB17 R2RB_IDL_17_12_TerB17
component class IDL_17_12_TerB18: CRB_IDL_17_12_TerB18 R1RB_IDL_17_12_TerB18 R2RB_IDL_17_12_TerB18
component class IDL_17_12_TerB19: CRB_IDL_17_12_TerB19 R1RB_IDL_17_12_TerB19 R2RB_IDL_17_12_TerB19
component class IDL_17_12_TerB20: CRB_IDL_17_12_TerB20 R1RB_IDL_17_12_TerB20 R2RB_IDL_17_12_TerB20
component class IDL_17_12_TerB21: CRB_IDL_17_12_TerB21 R1RB_IDL_17_12_TerB21 R2RB_IDL_17_12_TerB21
component class IDL_17_12_TerB22: CRB_IDL_17_12_TerB22 R1RB_IDL_17_12_TerB22 R2RB_IDL_17_12_TerB22
component class IDL_17_12_TerB23: CRB_IDL_17_12_TerB23 R1RB_IDL_17_12_TerB23 R2RB_IDL_17_12_TerB23
component class IDL_17_12_TerB24: CRB_IDL_17_12_TerB24 R1RB_IDL_17_12_TerB24 R2RB_IDL_17_12_TerB24
component class IDL_17_12_TerB25: CRB_IDL_17_12_TerB25 R1RB_IDL_17_12_TerB25 R2RB_IDL_17_12_TerB25
component class IDL_17_12_Top: 12V -3V3 -5V -12V R1 R2 R3 R4 R5 R6
net class JB[1..25]: JB1 JB2 JB3 JB4 JB5 JB6 JB7 JB8 JB9 JB10 JB11 JB12 JB13 JB14 JB15 JB16 JB17 JB18 JB19 JB20 JB21 JB22 JB23 JB24 JB25
net class JT[1..72]: JT1 JT2 JT3 JT4 JT5 JT6 JT7 JT8 JT9 JT10 JT11 JT12 JT13 JT14 JT15 JT16 JT17 JT18 JT19 JT20 JT21 JT22 JT23 JT24 JT25 JT26 JT27 JT28 JT29 JT30 JT31 JT32 JT33 JT34 JT35 JT36 JT37 JT38 JT39 JT40 JT41 JT42 JT43 JT44 JT45 JT46 JT47 JT48 JT49 JT50 JT51 JT52 JT53 JT54 JT55 JT56 JT57 JT58 JT59 JT60 JT61 JT62 JT63 JT64 JT65 JT66 JT67 JT68 JT69 JT70 JT71 JT72
channel class IDL_17_12_TerA: IDL_17_12_TerA1 IDL_17_12_TerA2 IDL_17_12_TerA3 IDL_17_12_TerA4 IDL_17_12_TerA5 IDL_17_12_TerA6 IDL_17_12_TerA7 IDL_17_12_TerA8 IDL_17_12_TerA9 IDL_17_12_TerA10 IDL_17_12_TerA11 IDL_17_12_TerA12 IDL_17_12_TerA13 IDL_17_12_TerA14 IDL_17_12_TerA15 IDL_17_12_TerA16 IDL_17_12_TerA17 IDL_17_12_TerA18 IDL_17_12_TerA19 IDL_17_12_TerA20 IDL_17_12_TerA21 IDL_17_12_TerA22 IDL_17_12_TerA23 IDL_17_12_TerA24 IDL_17_12_TerA25 IDL_17_12_TerA26 IDL_17_12_TerA27 IDL_17_12_TerA28 IDL_17_12_TerA29 IDL_17_12_TerA30 IDL_17_12_TerA31 IDL_17_12_TerA32 IDL_17_12_TerA33 IDL_17_12_TerA34 IDL_17_12_TerA35 IDL_17_12_TerA36 IDL_17_12_TerA37 IDL_17_12_TerA38 IDL_17_12_TerA39 IDL_17_12_TerA40 IDL_17_12_TerA41 IDL_17_12_TerA42 IDL_17_12_TerA43 IDL_17_12_TerA44 IDL_17_12_TerA45 IDL_17_12_TerA46 IDL_17_12_TerA47 IDL_17_12_TerA48 IDL_17_12_TerA49 IDL_17_12_TerA50 IDL_17_12_TerA51 IDL_17_12_TerA52 IDL_17_12_TerA53 IDL_17_12_TerA54 IDL_17_12_TerA55 IDL_17_12_TerA56 IDL_17_12_TerA57 IDL_17_12_TerA58 IDL_17_12_TerA59 IDL_17_12_TerA60 IDL_17_12_TerA61 IDL_17_12_TerA62 IDL_17_12_TerA63 IDL_17_12_TerA64 IDL_17_12_TerA65 IDL_17_12_TerA66 IDL_17_12_TerA67 IDL_17_12_TerA68 IDL_17_12_TerA69 IDL_17_12_TerA70 IDL_17_12_TerA71
channel class IDL_17_12_TerB: IDL_17_12_TerB1 IDL_17_12_TerB2 IDL_17_12_TerB3 IDL_17_12_TerB4 IDL_17_12_TerB5 IDL_17_12_TerB6 IDL_17_12_TerB7 IDL_17_12_TerB8 IDL_17_12_TerB9 IDL_17_12_TerB10 IDL_17_12_TerB11 IDL_17_12_TerB12 IDL_17_12_TerB13 IDL_17_12_TerB14 IDL_17_12_TerB15 IDL_17_12_TerB16 IDL_17_12_TerB17 IDL_17_12_TerB18 IDL_17_12_TerB19 IDL_17_12_TerB20 IDL_17_12_TerB21 IDL_17_12_TerB22 IDL_17_12_TerB23 IDL_17_12_TerB24 IDL_17_12_TerB25 IDL_17_12_TerB26 IDL_17_12_TerB27 IDL_17_12_TerB28 IDL_17_12_TerB29 IDL_17_12_TerB30 IDL_17_12_TerB31 IDL_17_12_TerB32 IDL_17_12_TerB33 IDL_17_12_TerB34 IDL_17_12_TerB35 IDL_17_12_TerB36 IDL_17_12_TerB37 IDL_17_12_TerB38 IDL_17_12_TerB39 IDL_17_12_TerB40 IDL_17_12_TerB41 IDL_17_12_TerB42 IDL_17_12_TerB43 IDL_17_12_TerB44 IDL_17_12_TerB45 IDL_17_12_TerB46 IDL_17_12_TerB47 IDL_17_12_TerB48 IDL_17_12_TerB49 IDL_17_12_TerB50 IDL_17_12_TerB51 IDL_17_12_TerB52 IDL_17_12_TerB53 IDL_17_12_TerB54 IDL_17_12_TerB55 IDL_17_12_TerB56 IDL_17_12_TerB57 IDL_17_12_TerB58 IDL_17_12_TerB59 IDL_17_12_TerB60 IDL_17_12_TerB61 IDL_17_12_TerB62 IDL_17_12_TerB63 IDL_17_12_TerB64 IDL_17_12_TerB65 IDL_17_12_TerB66 IDL_17_12_TerB67 IDL_17_12_TerB68 IDL_17_12_TerB69 IDL_17_12_TerB70 IDL_17_12_TerB71 IDL_17_12_TerB72 IDL_17_12_TerB73 IDL_17_12_TerB74 IDL_17_12_TerB75 IDL_17_12_TerB76 IDL_17_12_TerB77 IDL_17_12_TerB78 IDL_17_12_TerB79 IDL_17_12_TerB80 IDL_17_12_TerB81 IDL_17_12_TerB82 IDL_17_12_TerB83 IDL_17_12_TerB84 IDL_17_12_TerB85 IDL_17_12_TerB86 IDL_17_12_TerB87 IDL_17_12_TerB88

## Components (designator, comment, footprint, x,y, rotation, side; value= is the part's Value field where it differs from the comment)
3V3 "7701" PCBComponent_1 1488.84,6286.44 r0 top
3V3 "TP 0.5mm" TPH0.5S#1 1766.37,434.93 r90 bottom (schematic designator TP3V3)
5V "7701" PCBComponent_1 689.15,4347.73 r0 top
5V "TP 0.5mm" TPH0.5S#1 2272.26,9927.69 r90 bottom (schematic designator TP5V)
12V "7701" PCBComponent_1 2285.76,6285.77 r0 top
12V "TP 0.5mm" TPH0.5S#1 1247.83,434.61 r90 bottom (schematic designator TP12V)
-3V3 "7701" PCBComponent_1 2285.87,4348.54 r0 top
-3V3 "TP 0.5mm" TPH0.5S#1 2867.29,9946.36 r90 bottom (schematic designator TP-3V3)
-5V "7701" PCBComponent_1 1483.08,3476.61 r0 top
-5V "TP 0.5mm" TPH0.5S#1 2571.02,9932.41 r90 bottom (schematic designator TP-5V)
-12V "7701" PCBComponent_1 691.41,6274.77 r0 top
-12V "TP 0.5mm" TPH0.5S#2 623.25,418.16 r90 bottom (schematic designator TP-12V)
-12V "TP 0.5mm" TPH0.5S#1 921.62,416.17 r90 bottom (schematic designator TP3V3)
AS "Comment" TPH0.5S#3 900.18,7661.5 r180 bottom
BERR "Comment" TPH0.5S#3 2387.48,8356.01 r180 bottom
CR_IDL_17_12_TerA1 "1uF" CC0402N1X 3079.72,6438.88 r270 bottom (schematic designator CR)
CR_IDL_17_12_TerA2 "1uF" CC0402N1X 3074.72,6550.11 r270 bottom (schematic designator CR)
CR_IDL_17_12_TerA3 "1uF" CC0402N1X 3074.72,6655.11 r270 bottom (schematic designator CR)
CR_IDL_17_12_TerA4 "1uF" CC0402N1X 3074.72,6760.11 r270 bottom (schematic designator CR)
CR_IDL_17_12_TerA5 "1uF" CC0402N1X 3074.72,6865.11 r270 bottom (schematic designator CR)
CR_IDL_17_12_TerA6 "1uF" CC0402N1X 3074.72,6970.11 r270 bottom (schematic designator CR)
CR_IDL_17_12_TerA7 "1uF" CC0402N1X 3074.72,7075.11 r270 bottom (schematic designator CR)
CR_IDL_17_12_TerA8 "1uF" CC0402N1X 3074.72,7180.11 r270 bottom (schematic designator CR)
CR_IDL_17_12_TerA9 "1uF" CC0402N1X 3074.72,7445.11 r270 bottom (schematic designator CR)
CR_IDL_17_12_TerA10 "1uF" CC0402N1X 3074.72,7645.11 r270 bottom (schematic designator CR)
CR_IDL_17_12_TerA11 "1uF" CC0402N1X 3074.72,7840.11 r270 bottom (schematic designator CR)
CR_IDL_17_12_TerA12 "1uF" CC0402N1X 3074.35,8023.33 r270 bottom (schematic designator CR)
CR_IDL_17_12_TerA13 "1uF" CC0402N1X 3074.35,8128.33 r270 bottom (schematic designator CR)
CR_IDL_17_12_TerA14 "1uF" CC0402N1X 3074.35,8233.33 r270 bottom (schematic designator CR)
CR_IDL_17_12_TerA15 "1uF" CC0402N1X 3080.36,8453.27 r270 bottom (schematic designator CR)
CR_IDL_17_12_TerA16 "1uF" CC0402N1X 3086.06,8633.97 r270 bottom (schematic designator CR)
CR_IDL_17_12_TerA17 "1uF" CC0402N1X 3086.06,8736.97 r270 bottom (schematic designator CR)
CR_IDL_17_12_TerA18 "1uF" CC0402N1X 3086.06,8841.97 r270 bottom (schematic designator CR)
CR_IDL_17_12_TerA19 "1uF" CC0402N1X 3086.06,8946.97 r270 bottom (schematic designator CR)
CR_IDL_17_12_TerA20 "1uF" CC0402N1X 3086.06,9051.97 r270 bottom (schematic designator CR)
CR_IDL_17_12_TerA21 "1uF" CC0402N1X 3086.06,9156.97 r270 bottom (schematic designator CR)
CR_IDL_17_12_TerA22 "1uF" CC0402N1X 3086.06,9261.97 r270 bottom (schematic designator CR)
CR_IDL_17_12_TerA23 "1uF" CC0402N1X 3086.06,9366.97 r270 bottom (schematic designator CR)
CR_IDL_17_12_TerA24 "1uF" CC0402N1X 1587.86,6461.21 r270 top (schematic designator CR)
CR_IDL_17_12_TerA25 "1uF" CC0402N1X 1587.86,6566.21 r270 top (schematic designator CR)
CR_IDL_17_12_TerA26 "1uF" CC0402N1X 1587.86,6671.21 r270 top (schematic designator CR)
CR_IDL_17_12_TerA27 "1uF" CC0402N1X 1587.86,6776.21 r270 top (schematic designator CR)
CR_IDL_17_12_TerA28 "1uF" CC0402N1X 1587.86,6881.21 r270 top (schematic designator CR)
CR_IDL_17_12_TerA29 "1uF" CC0402N1X 1587.86,6986.21 r270 top (schematic designator CR)
CR_IDL_17_12_TerA30 "1uF" CC0402N1X 1587.86,7091.21 r270 top (schematic designator CR)
CR_IDL_17_12_TerA31 "1uF" CC0402N1X 1587.86,7196.21 r270 top (schematic designator CR)
CR_IDL_17_12_TerA32 "1uF" CC0402N1X 1587.86,7304.21 r270 top (schematic designator CR)
CR_IDL_17_12_TerA33 "1uF" CC0402N1X 1588.81,7545.11 r270 top (schematic designator CR)
CR_IDL_17_12_TerA34 "1uF" CC0402N1X 1588.81,7650.11 r270 top (schematic designator CR)
CR_IDL_17_12_TerA35 "1uF" CC0402N1X 1588.81,7755.11 r270 top (schematic designator CR)
CR_IDL_17_12_TerA36 "1uF" CC0402N1X 1588.81,7860.11 r270 top (schematic designator CR)
CR_IDL_17_12_TerA37 "1uF" CC0402N1X 1588.81,7965.11 r270 top (schematic designator CR)
CR_IDL_17_12_TerA38 "1uF" CC0402N1X 1588.81,8070.11 r270 top (schematic designator CR)
CR_IDL_17_12_TerA39 "1uF" CC0402N1X 1588.81,8175.11 r270 top (schematic designator CR)
CR_IDL_17_12_TerA40 "1uF" CC0402N1X 1588.81,8280.11 r270 top (schematic designator CR)
CR_IDL_17_12_TerA41 "1uF" CC0402N1X 1601.86,9150.08 r270 top (schematic designator CR)
CR_IDL_17_12_TerA42 "1uF" CC0402N1X 1601.86,9250.08 r270 top (schematic designator CR)
CR_IDL_17_12_TerA43 "1uF" CC0402N1X 1601.79,9373.04 r270 top (schematic designator CR)
CR_IDL_17_12_TerA44 "1uF" CC0402N1X 96.11,6427.54 r270 bottom (schematic designator CR)
CR_IDL_17_12_TerA45 "1uF" CC0402N1X 96.11,6532.54 r270 bottom (schematic designator CR)
CR_IDL_17_12_TerA46 "1uF" CC0402N1X 96.11,6637.54 r270 bottom (schematic designator CR)
CR_IDL_17_12_TerA47 "1uF" CC0402N1X 96.11,6740.54 r270 bottom (schematic designator CR)
CR_IDL_17_12_TerA48 "1uF" CC0402N1X 96.11,6845.54 r270 bottom (schematic designator CR)
CR_IDL_17_12_TerA49 "1uF" CC0402N1X 96.11,6950.54 r270 bottom (schematic designator CR)
CR_IDL_17_12_TerA50 "1uF" CC0402N1X 96.11,7055.54 r270 bottom (schematic designator CR)
CR_IDL_17_12_TerA51 "1uF" CC0402N1X 96.11,7160.54 r270 bottom (schematic designator CR)
CR_IDL_17_12_TerA52 "1uF" CC0402N1X 96.11,7265.54 r270 bottom (schematic designator CR)
CR_IDL_17_12_TerA53 "1uF" CC0402N1X 96.11,7370.54 r270 bottom (schematic designator CR)
CR_IDL_17_12_TerA54 "1uF" CC0402N1X 96.11,7475.54 r270 bottom (schematic designator CR)
CR_IDL_17_12_TerA55 "1uF" CC0402N1X 96.11,7580.54 r270 bottom (schematic designator CR)
CR_IDL_17_12_TerA56 "1uF" CC0402N1X 96.11,7685.54 r270 bottom (schematic designator CR)
CR_IDL_17_12_TerA57 "1uF" CC0402N1X 96.11,7790.54 r270 bottom (schematic designator CR)
CR_IDL_17_12_TerA58 "1uF" CC0402N1X 96.11,7895.54 r270 bottom (schematic designator CR)
CR_IDL_17_12_TerA59 "1uF" CC0402N1X 96.11,8000.54 r270 bottom (schematic designator CR)
CR_IDL_17_12_TerA60 "1uF" CC0402N1X 96.11,8105.54 r270 bottom (schematic designator CR)
CR_IDL_17_12_TerA61 "1uF" CC0402N1X 96.11,8210.54 r270 bottom (schematic designator CR)
CR_IDL_17_12_TerA62 "1uF" CC0402N1X 96.11,8318.54 r270 bottom (schematic designator CR)
CR_IDL_17_12_TerA63 "1uF" CC0402N1X 96.11,8423.54 r270 bottom (schematic designator CR)
CR_IDL_17_12_TerA64 "1uF" CC0402N1X 96.11,8528.54 r270 bottom (schematic designator CR)
CR_IDL_17_12_TerA65 "1uF" CC0402N1X 96.11,8633.54 r270 bottom (schematic designator CR)
CR_IDL_17_12_TerA66 "1uF" CC0402N1X 96.11,8738.54 r270 bottom (schematic designator CR)
CR_IDL_17_12_TerA67 "1uF" CC0402N1X 96.11,8843.54 r270 bottom (schematic designator CR)
CR_IDL_17_12_TerA68 "1uF" CC0402N1X 96.11,8948.54 r270 bottom (schematic designator CR)
CR_IDL_17_12_TerA69 "1uF" CC0402N1X 96.11,9053.54 r270 bottom (schematic designator CR)
CR_IDL_17_12_TerA70 "1uF" CC0402N1X 96.11,9158.54 r270 bottom (schematic designator CR)
CR_IDL_17_12_TerA71 "1uF" CC0402N1X 96.11,9263.54 r270 bottom (schematic designator CR)
CR_IDL_17_12_TerA72 "1uF" CC0402N1X 97.41,9376.01 r270 bottom (schematic designator CR)
CRB_IDL_17_12_TerB1 "1uF" CC0402N1X 115.13,1234.14 r270 bottom (schematic designator CRB)
CRB_IDL_17_12_TerB2 "1uF" CC0402N1X 114.44,1341.61 r270 bottom (schematic designator CRB)
CRB_IDL_17_12_TerB3 "1uF" CC0402N1X 114.44,1446.61 r270 bottom (schematic designator CRB)
CRB_IDL_17_12_TerB4 "1uF" CC0402N1X 114.44,1546.61 r270 bottom (schematic designator CRB)
CRB_IDL_17_12_TerB5 "1uF" CC0402N1X 114.44,1646.61 r270 bottom (schematic designator CRB)
CRB_IDL_17_12_TerB6 "1uF" CC0402N1X 114.44,1746.61 r270 bottom (schematic designator CRB)
CRB_IDL_17_12_TerB7 "1uF" CC0402N1X 114.44,1849.61 r270 bottom (schematic designator CRB)
CRB_IDL_17_12_TerB8 "1uF" CC0402N1X 114.44,1949.61 r270 bottom (schematic designator CRB)
CRB_IDL_17_12_TerB9 "1uF" CC0402N1X 114.44,2049.61 r270 bottom (schematic designator CRB)
CRB_IDL_17_12_TerB10 "1uF" CC0402N1X 114.44,2149.61 r270 bottom (schematic designator CRB)
CRB_IDL_17_12_TerB11 "1uF" CC0402N1X 114.44,2254.61 r270 bottom (schematic designator CRB)
CRB_IDL_17_12_TerB12 "1uF" CC0402N1X 114.44,2354.61 r270 bottom (schematic designator CRB)
CRB_IDL_17_12_TerB13 "1uF" CC0402N1X 114.44,2454.61 r270 bottom (schematic designator CRB)
CRB_IDL_17_12_TerB14 "1uF" CC0402N1X 114.44,2554.61 r270 bottom (schematic designator CRB)
CRB_IDL_17_12_TerB15 "1uF" CC0402N1X 114.44,2654.61 r270 bottom (schematic designator CRB)
CRB_IDL_17_12_TerB16 "1uF" CC0402N1X 114.44,2759.61 r270 bottom (schematic designator CRB)
CRB_IDL_17_12_TerB17 "1uF" CC0402N1X 114.44,2859.61 r270 bottom (schematic designator CRB)
CRB_IDL_17_12_TerB18 "1uF" CC0402N1X 114.44,2959.61 r270 bottom (schematic designator CRB)
CRB_IDL_17_12_TerB19 "1uF" CC0402N1X 114.44,3059.61 r270 bottom (schematic designator CRB)
CRB_IDL_17_12_TerB20 "1uF" CC0402N1X 114.44,3164.61 r270 bottom (schematic designator CRB)
CRB_IDL_17_12_TerB21 "1uF" CC0402N1X 114.44,3264.61 r270 bottom (schematic designator CRB)
CRB_IDL_17_12_TerB22 "1uF" CC0402N1X 114.44,3362.61 r270 bottom (schematic designator CRB)
CRB_IDL_17_12_TerB23 "1uF" CC0402N1X 114.44,3462.61 r270 bottom (schematic designator CRB)
CRB_IDL_17_12_TerB24 "1uF" CC0402N1X 114.44,3567.61 r270 bottom (schematic designator CRB)
CRB_IDL_17_12_TerB25 "1uF" CC0402N1X 114.44,3667.61 r270 bottom (schematic designator CRB)
DTACK "Comment" TPH0.5S#4 2363.27,7855.28 r180 bottom
GND "Comment" TPH0.5S#5 2068.25,9890.07 r180 bottom
GND "7701" PCBComponent_1 1486.99,4347.79 r0 top
GND "Comment" TPH0.5S#5 1527.87,429.55 r180 bottom
Jbot1 "" 0903296x825 2788.16,2554.97 r270 top
Jbot2 "" 0903296x825 1988.16,2554.97 r270 top
Jbot3 "" 0903296x825 1188.16,2554.97 r270 top
Jbot4 "" 0903296x825 388.16,2554.97 r270 top
JMid1 "" "127-Pin Conncector" 2718.96,5155.23 r270 top
JMid2 "" "127-Pin Conncector" 1918.96,5155.23 r270 top
JMid3 "" "127-Pin Conncector" 1118.96,5155.23 r270 top
JMid4 "" "127-Pin Conncector" 318.96,5155.23 r270 top
Jtop1 "" 0903296x825 2788.16,7804.97 r270 top
Jtop2 "" 0903296x825 1988.16,7804.97 r270 top
Jtop3 "" 0903296x825 1188.16,7804.97 r270 top
Jtop4 "" 0903296x825 388.16,7804.97 r270 top
R1 "0R0" RC0402N1R 2686.24,9931.73 r0 top
R1R_IDL_17_12_TerA1 "499R" RC0402N1R 3009.11,6412.3 r0 bottom (schematic designator R1R)
R1R_IDL_17_12_TerA2 "499R" RC0402N1R 3004.11,6523.54 r0 bottom (schematic designator R1R)
R1R_IDL_17_12_TerA3 "499R" RC0402N1R 3004.11,6628.54 r0 bottom (schematic designator R1R)
R1R_IDL_17_12_TerA4 "499R" RC0402N1R 3004.11,6733.54 r0 bottom (schematic designator R1R)
R1R_IDL_17_12_TerA5 "499R" RC0402N1R 3004.11,6838.54 r0 bottom (schematic designator R1R)
R1R_IDL_17_12_TerA6 "499R" RC0402N1R 3004.11,6943.54 r0 bottom (schematic designator R1R)
R1R_IDL_17_12_TerA7 "499R" RC0402N1R 3004.11,7048.54 r0 bottom (schematic designator R1R)
R1R_IDL_17_12_TerA8 "499R" RC0402N1R 3004.11,7153.54 r0 bottom (schematic designator R1R)
R1R_IDL_17_12_TerA9 "499R" RC0402N1R 3004.11,7418.54 r0 bottom (schematic designator R1R)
